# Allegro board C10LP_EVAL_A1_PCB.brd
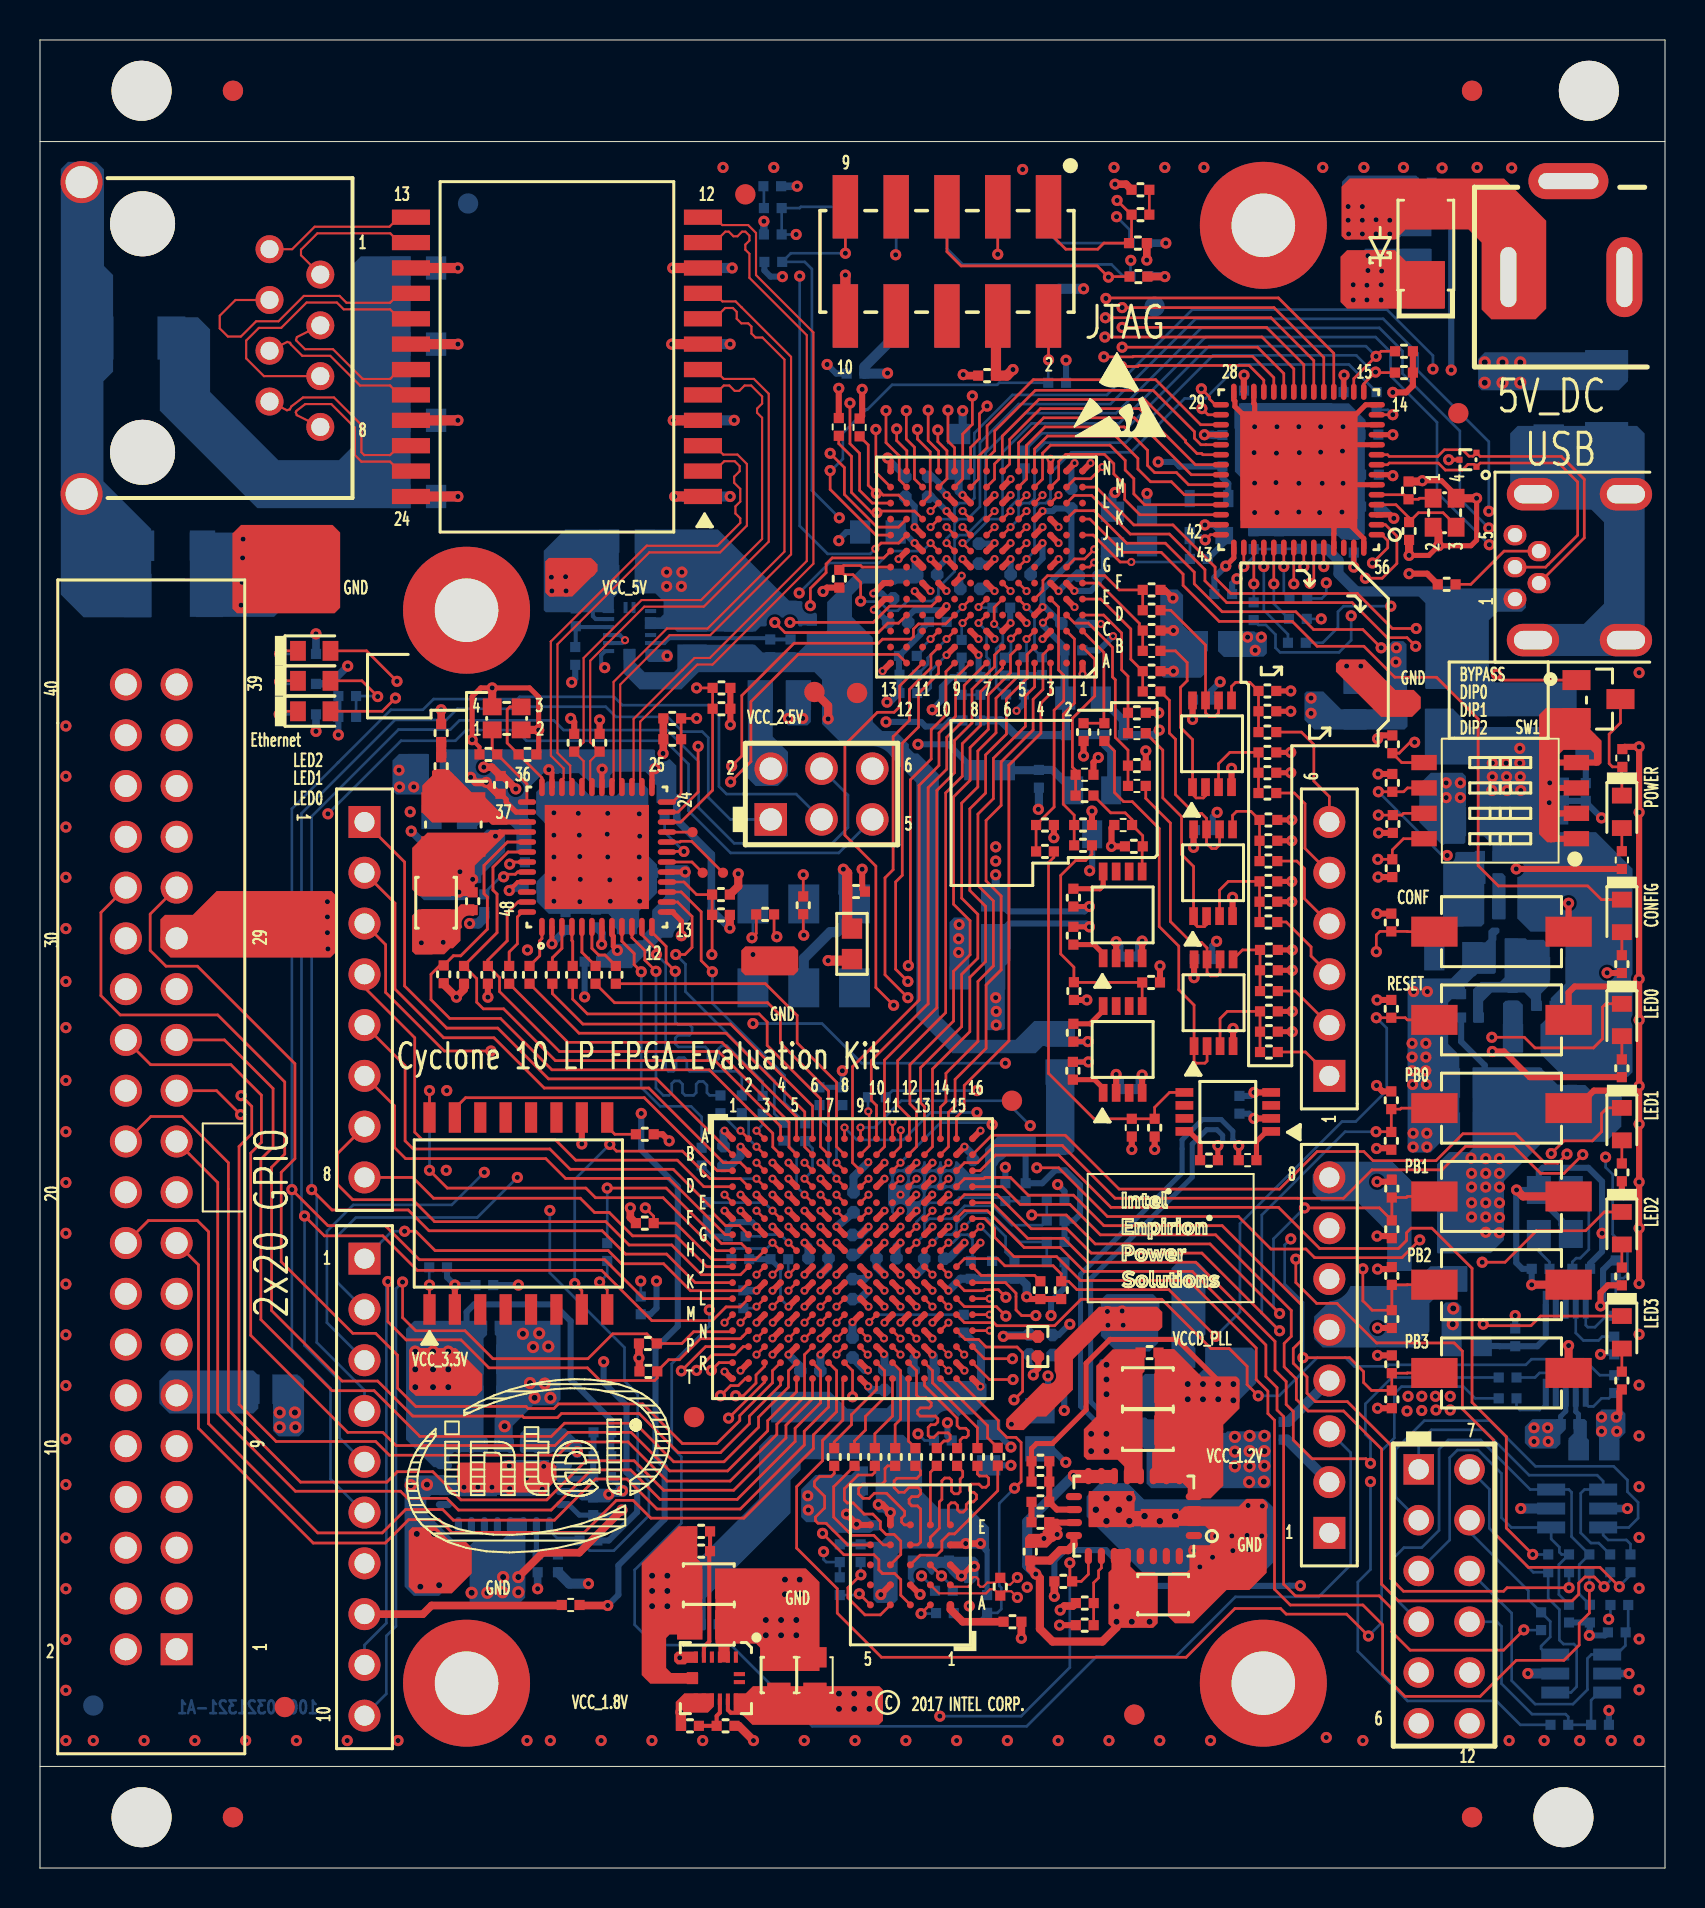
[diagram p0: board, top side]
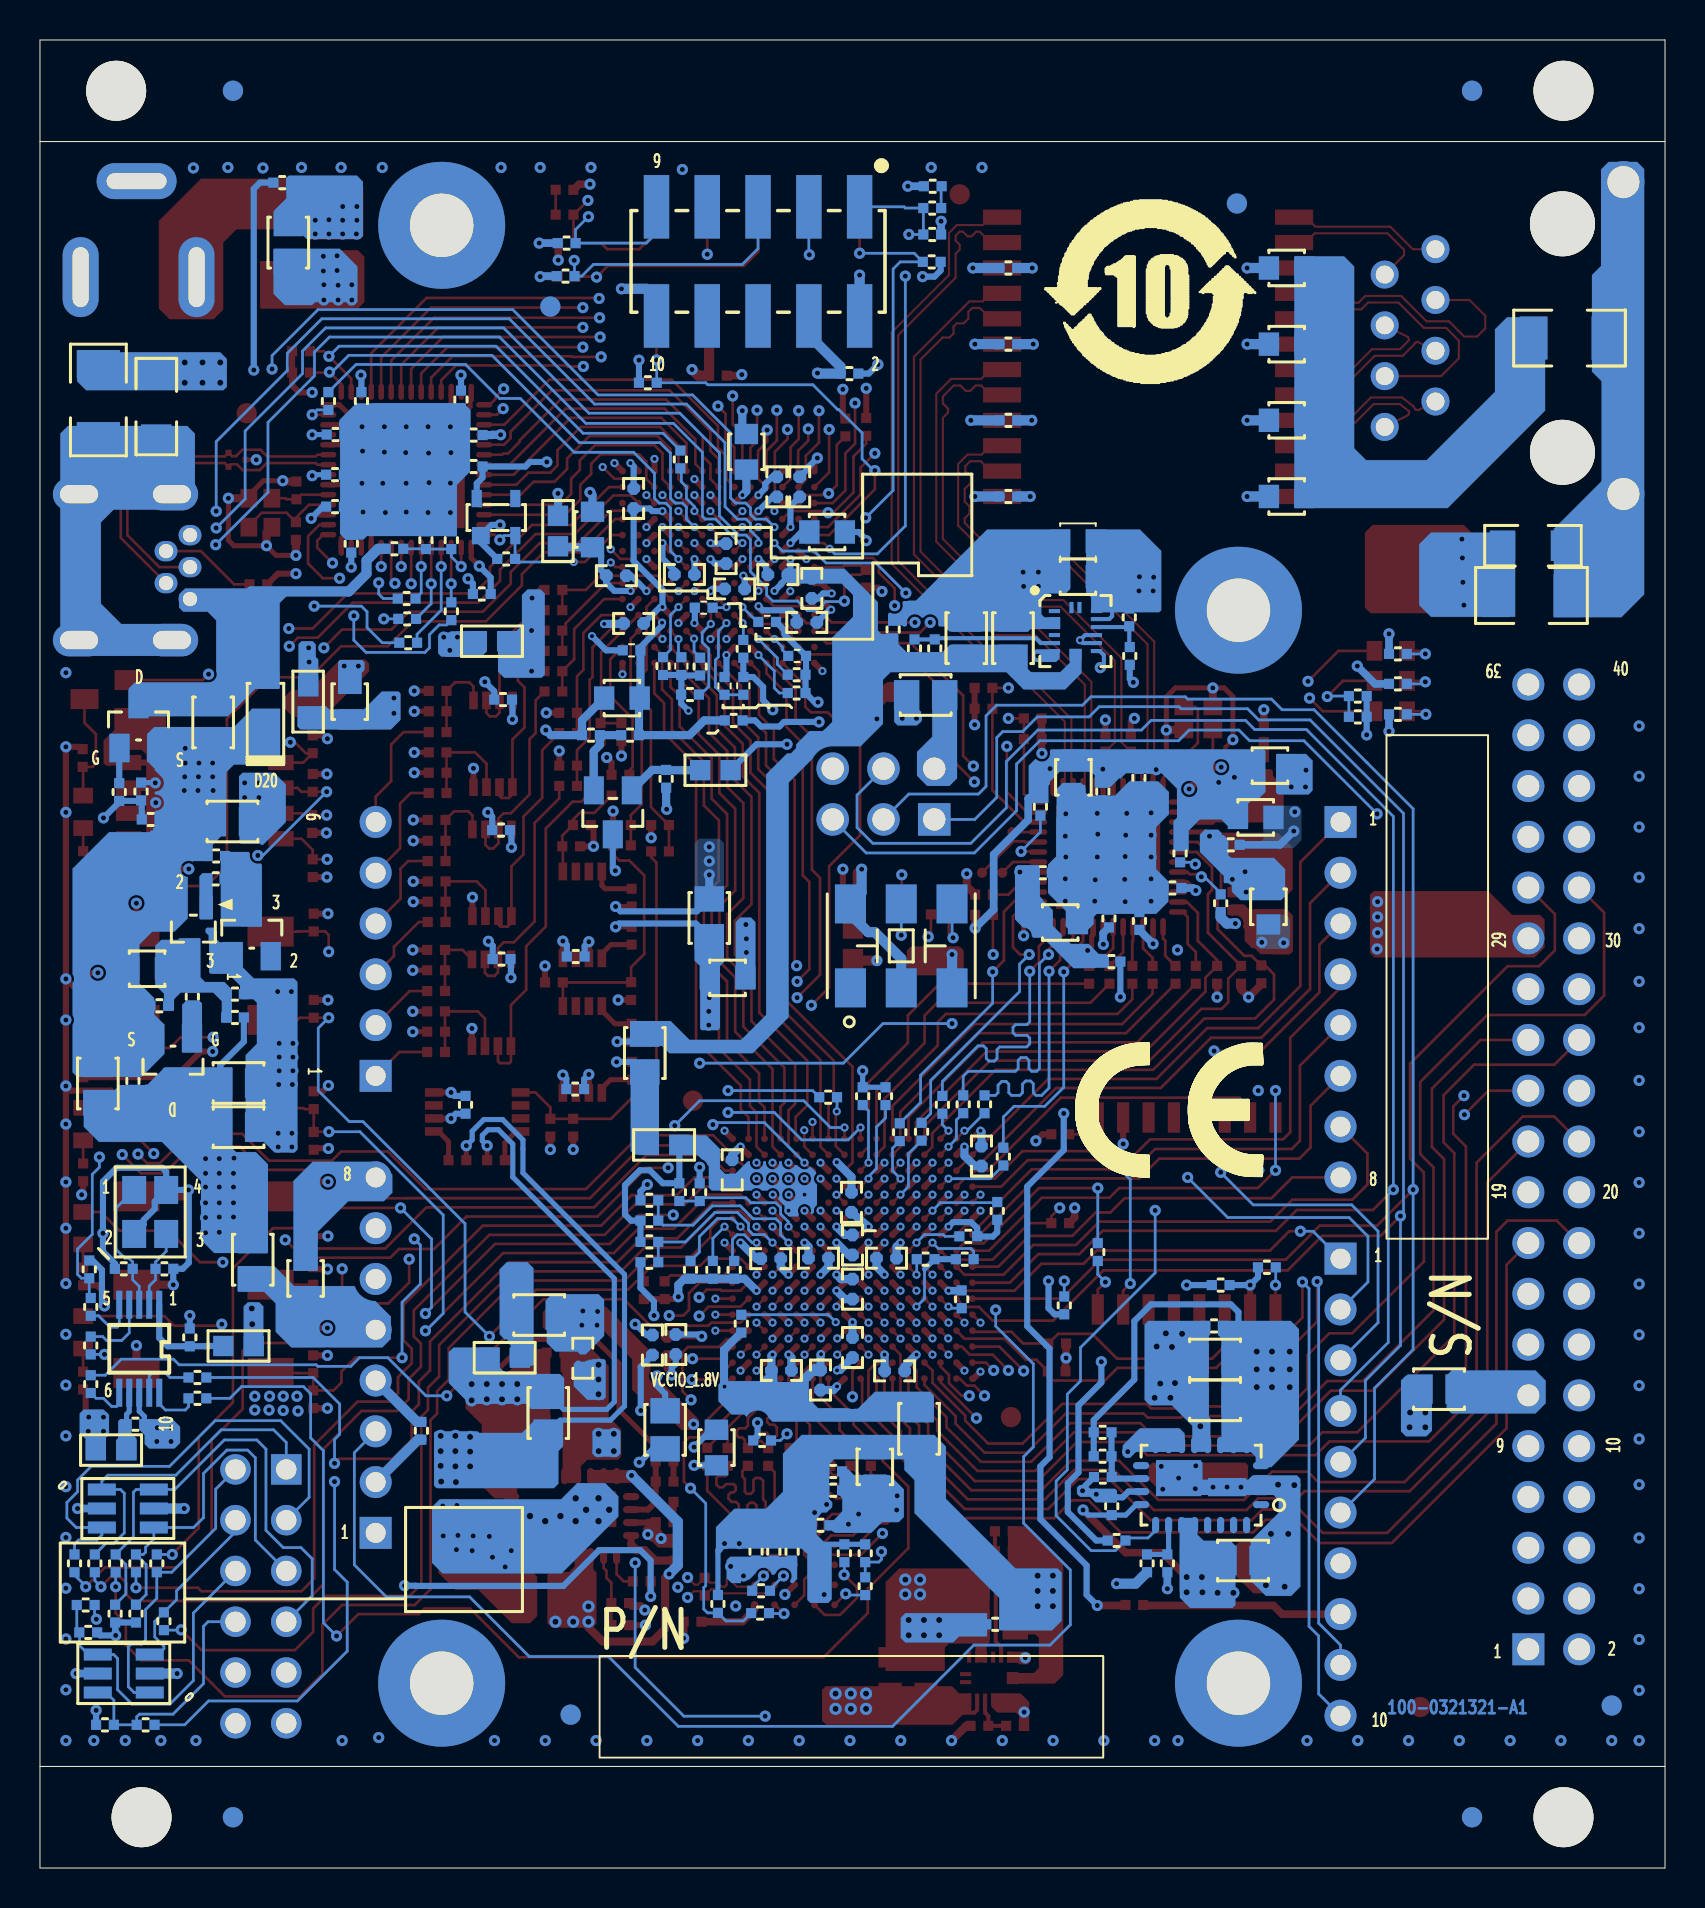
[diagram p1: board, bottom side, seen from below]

Outline 81.28 x 91.44 mm; copper layers: TOP, GND02, ART03, VCC04, GND05, BOTTOM. Coordinates in mm from the lower left corner of the outline.
Outline path: 0,86.36 81.28,86.36 ; 0,5.08 81.28,5.08 ; 0,91.44 0,0 81.28,0 81.28,91.44 0,91.44

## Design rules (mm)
net group C10_CLK50M: nets C10_CLK50M C10_CLK50M_R
net group C10_MSEL1: nets C10_MSEL1 C10_VCCA_FLT
net group DP_FX2_D_: nets FX2_D_N FX2_D_P
net group EXT_JTAG_TCK: nets EXT_JTAG_TCK N17451710
net group HBUS_CKP/HBUS_CKN: nets HBUS_CKN HBUS_CKP
net group HBUS_CS1N: nets HBUS_CS1N N17204392
net group HBUS_DQ0: nets HBUS_DQ0 N17132385
net group HBUS_DQ1: nets HBUS_DQ1 N17132392
net group HBUS_DQ2: nets HBUS_DQ2 N17132399
net group HBUS_DQ3: nets HBUS_DQ3 N17132406
net group HBUS_DQ4: nets HBUS_DQ4 N17132413
net group HBUS_DQ5: nets HBUS_DQ5 N17132420
net group HBUS_DQ6: nets HBUS_DQ6 N17132427
net group HBUS_DQ7: nets HBUS_DQ7 N17132434
net group HBUS_INTN: nets HBUS_INTN N17217865
net group HBUS_RSTON: nets HBUS_RSTON N17217821
net group HBUS_RWDS: nets HBUS_RWDS N17132441
net group M10_CLK50M: nets M10_CLK50M M10_CLK50M_R
net group M10_TCK: nets M10_TCK N16798884
net group MX1+/MX1-: nets MX1+ MX1-
net group MX2+/MX2-: nets MX2+ MX2-
net group MX3+/MX3-: nets MX3+ MX3-
net group MX4+/MX4-: nets MX4+ MX4-
net group TPIAP/TPIAN: nets TPIAN TPIAP
net group TPIBP/TPIBN: nets TPIBN TPIBP
net group TPICP/TPICN: nets TPICN TPICP
net group TPIDP/TPIDN: nets TPIDN TPIDP
net group C10_RG_TXCLK: nets ENET_RG_TXCLK
net group C10_RG_TXCTL: nets ENET_RG_TXCTL
net group C10_RG_TXD0: nets ENET_RG_TXD0
net group C10_RG_TXD1: nets ENET_RG_TXD1
net group C10_RG_TXD2: nets ENET_RG_TXD2
net group C10_RG_TXD3: nets ENET_RG_TXD3
net group CLS_I2C: nets ARDUINO_ADC_SCL ARDUINO_ADC_SDA ARDUINO_SCL ARDUINO_SDA FX2_SCL FX2_SDA MAX_SDA SYS_I2C_SCL SYS_I2C_SDA USB_SCL USB_SDA
net group ENET_RG_RX: nets RG_RXCLK RG_RXCTL RG_RXD0 RG_RXD1 RG_RXD2 RG_RXD3
net group ENET_RG_RXCLK: nets ENET_RG_RXCLK
net group ENET_RG_RXCTL: nets ENET_RG_RXCTL
net group ENET_RG_RXD0: nets ENET_RG_RXD0
net group ENET_RG_RXD1: nets ENET_RG_RXD1
net group ENET_RG_RXD2: nets ENET_RG_RXD2
net group ENET_RG_RXD3: nets ENET_RG_RXD3
net group ENET_RG_TX: nets C10_RG_TXCLK C10_RG_TXCTL C10_RG_TXD0 C10_RG_TXD1 C10_RG_TXD2 C10_RG_TXD3
net group EXT_VREF_AR: nets EXT_VREF EXT_VREF_AR N17512425

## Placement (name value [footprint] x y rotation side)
C1  0.1uF  [0402]  22.23 29.16 270 bottom
C2  0.1uF  [0402]  59.59 70.1 90 bottom
C4  12pF  [0402]  68.45 68.91 180 top
C5  12pF  [0402]  68.48 66.88 0 top
C6  0.1uF  [0402]  65.71 66.24 180 bottom
C7  0.1uF  [0402]  66.52 69.7 270 bottom
C8  0.1uF  [0402]  59.59 71.68 90 bottom
C9  0.1uF  [0402]  60.22 73.46 0 bottom
C10  0.1uF  [0402]  66.5 71.7 270 bottom
C11  0.1uF  [0402]  59.18 63.73 90 bottom
C12  0.1uF  [0402]  66.52 68.1 270 bottom
C13  0.1uF  [0402]  65.2 73.38 0 bottom
C14  0.1uF  [0402]  60.71 66.42 180 bottom
C15  DNI  [0402]  36.63 84.12 90 bottom
C16  0.1uF  [0402]  40.79 74.75 270 bottom
C17  0.1uF  [0402]  55.04 83.95 90 top
C18  0.1uF  [0402]  47.37 74.65 90 top
C19  0.1uF  [0402]  59.99 38.18 180 bottom
C20  DNI  [0402]  55.75 37.03 180 top
C22  DNI  [0402]  55.58 44.3 270 top
C23  0.1uF  [0402]  54.51 38.96 90 bottom
C26  0.1uF  [0402]  54.48 45.59 90 bottom
C28  DNI  [0402]  54.71 51.1 90 top
C29  1pF  [0402]  54.86 55.14 90 top
C30  DNI  [0402]  49.96 54.48 180 bottom
C31  DNI  [0402]  53.72 56.67 270 bottom
C32  1pF  [0402]  54.86 57.78 90 top
C33  1pF  [0402]  52.17 52.17 90 top
C34  1pF  [0402]  50.27 52.17 90 top
C35  1pF  [0402]  55.6 63.93 90 top
C36  1pF  [0402]  52.2 56.82 0 top
C37  1pF  [0402]  52.25 54.69 90 top
C38  1pF  [0402]  55.6 61.9 90 top
C39  1pF  [0402]  55.6 59.87 90 top
C40  10uF  [0603]  39.52 20.07 270 bottom
C41  0.1uF  [0402]  42.24 17.14 270 bottom
C42  0.1uF  [0402]  44.58 15.82 0 bottom
C43  0.1uF  [0402]  45.47 15.82 0 bottom
C44  27pF  [0402]  24.38 55.7 90 top
C45  22uF  [0805]  19.81 48.29 90 top
C46  330pF  [0402]  21.64 48.36 0 top
C47  330pF  [0402]  20.07 56.77 180 top
C48  10uF  [0603]  30.25 47.29 180 bottom
C49  10uF  [0603]  19.84 48.08 270 bottom
C50  0.1uF  [0402]  31.11 49.78 270 bottom
C51  0.1uF  [0402]  27.69 45.34 270 bottom
C52  0.1uF  [0402]  21.72 51.18 270 bottom
C53  27pF  [0402]  22.43 55.7 270 top
C54  DNI  [0402]  34.06 48.69 270 top
C55  DNI  [0402]  31.62 57.51 90 top
C56  DNI  [0402]  15.37 57.58 270 bottom
C57  0.1uF  [0402]  26.31 54.53 0 bottom
C58  0.1uF  [0402]  28.12 53.85 0 bottom
C59  10uF  [0603]  29.59 54.56 270 bottom
C60  0.1uF  [0402]  24.64 49.02 90 bottom
C61  0.1uF  [0402]  26.29 47.37 180 bottom
C62  0.1uF  [0402]  27.81 47.5 180 bottom
C63  10uF  [0603]  20.47 52.55 180 bottom
C64  0.1uF  [0402]  23.04 54.18 0 top
C65  DNI  [0402]  34.09 57.99 270 top
C66  DNI  [0402]  75.06 29.97 270 bottom
C67  0.1uF  [0402]  73.79 26.54 180 bottom
C72  0.1uF  [0402]  76.5 22.2 270 bottom
C73  DNI  [0402]  77.09 29.97 90 bottom
C74  0.1uF  [0402]  40.82 48.84 270 top
C76  47uF  [0805]  71.35 37.06 180 bottom
C83  22uF  [0805]  21.11 15.38 180 bottom
C84  8.2pF  [0402]  28.13 20.6 90 bottom
C85  47uF  [0805]  22.5 25.44 0 bottom
C86  47uF  [0805]  22.5 23.39 0 bottom
C87  DNI  [0402]  22.56 27.11 270 bottom
C88  DNI  [0402]  24.89 15.24 0 bottom
C89  1uF  [0402]  27.67 18.1 0 bottom
C96  22uF  [0805]  56.18 13.68 0 top
C97  8.2pF  [0402]  50.04 19.33 90 top
C98  22uF  [0805]  55.41 21.9 180 top
C99  22uF  [0805]  55.41 24 180 top
C100  DNI  [0402]  55.5 25.78 270 top
C101  DNI  [0402]  52.26 13.25 90 top
C102  1uF  [0402]  49.53 15.82 180 top
C103  DNI  [0402]  36.53 61.01 0 bottom
C104  DNI  [0402]  33.07 16.84 90 top
C105  4.7uF  [0603]  36.96 9.65 90 top
C106  4.7uF  [0603]  29.36 64.59 0 bottom
C107  10uF  [0805]  33.45 12.17 0 top
C108  10uF  [0805]  33.45 14.2 0 top
C109  10uF  [0805]  32.61 61.52 90 bottom
C110  10uF  [0805]  34.95 61.52 90 bottom
C111  DNI  [0402]  38.61 61.95 0 bottom
C112  DNI  [0402]  33.5 12.19 270 bottom
C113  DNI  [0402]  26.77 60.63 0 bottom
C114  DNI  [0402]  34.29 7.11 270 top
C115  1uF  [C0402_BGA]  54.13 25.5 270 bottom
C117  0.1uF  [C0402_BGA]  46.66 34.92 270 bottom
C120  0.01uF  [C0402_BGA]  34.19 35.61 90 bottom
C122  0.01uF  [C0402_BGA]  44.2 24.89 0 bottom
C124  0.022uF  [C0402_BGA]  40.69 33.3 90 bottom
C129  0.022uF  [C0402_BGA]  40.64 26.03 270 bottom
C130  1uF  [C0402_BGA]  49.48 26.19 270 bottom
C134  4700pF  [C0402_BGA]  40.64 28.96 90 bottom
C136  4700pF  [C0402_BGA]  44.73 30.48 0 bottom
C138  0.01uF  [C0402_BGA]  42.34 30.51 0 bottom
C139  0.01uF  [C0402_BGA]  38.94 30.51 180 bottom
C141  0.047uF  [C0402_BGA]  40.64 31.17 270 bottom
C142  0.22uF  [C0402_BGA]  50.65 26.16 270 bottom
C143  0.1uF  [C0402_BGA]  49.91 26.09 90 top
C146  4.7uF  [0603]  41.91 66.83 180 bottom
C151  0.047uF  [C0402_BGA]  46.53 63.98 180 bottom
C153  0.01uF  [C0402_BGA]  46.96 65.75 90 bottom
C155  0.01uF  [C0402_BGA]  43.28 69.09 270 bottom
C156  0.22uF  [C0402_BGA]  52.45 64.64 180 bottom
C157  0.01uF  [C0402_BGA]  49.05 64.71 180 bottom
C159  1nF/3kV  [1808]  4.78 76.53 180 bottom
C160  68pF  [0402]  32.84 80.04 270 bottom
C161  68pF  [0402]  32.84 76.23 270 bottom
C162  68pF  [0402]  32.84 72.42 270 bottom
C163  68pF  [0402]  32.84 68.61 270 bottom
C164  1nF/3kV  [1808]  6.68 63.65 0 bottom
C165  DNI  [0603]  29.36 66.37 0 bottom
C166  DNI  [0603]  38.76 9.65 90 top
C168  0.1uF  [0402]  58.19 45.47 270 bottom
C169  1nF  [0402]  61.47 42.85 90 top
C170  1nF  [0402]  61.47 45.92 90 top
C171  1nF  [0402]  61.44 49.35 90 top
C172  1nF  [0402]  61.44 52.43 90 top
C173  0.1uF  [0402]  58.22 51.92 270 bottom
C174  1nF  [0402]  61.39 55.8 90 top
C175  1nF  [0402]  61.39 58.88 90 top
C176  10uF  [0603]  53.64 66.95 90 bottom
C177  10uF  [0603]  65.79 58.34 90 bottom
C178  0.1uF  [C0402_BGA]  51.59 68.5 270 bottom
C179  0.1uF  [C0402_BGA]  42.93 62.31 0 bottom
C180  0.1uF  [C0402_BGA]  44.42 69.09 270 bottom
C181  0.1uF  [C0402_BGA]  51.59 62.26 180 bottom
C182  1uF  [C0402_BGA]  44.37 64.69 0 bottom
C183  1uF  [0402]  43.66 15.82 180 bottom
C184  0.1uF  [0402]  41.61 19.84 270 bottom
C185  1uF  [0402]  41.61 18.9 90 bottom
C188  0.1uF  [0402]  58.12 58.45 270 bottom
C189  0.22uF  [C0402_BGA]  42.67 64.01 270 bottom
C190  4.7uF  [0603]  45.95 70.84 90 bottom
C193  47uF  [0805]  50.01 21.92 270 bottom
C194  4.7uF  [0603]  47.45 21.03 270 bottom
C195  4.7uF  [0603]  46.89 44.53 180 bottom
C196  0.47uF  [C0402_BGA]  38.53 24.87 180 bottom
C197  1uF  [C0402_BGA]  42.24 24.41 270 bottom
C200  DNI  [0402]  71.53 42.55 90 bottom
C201  1uF  [0603]  75.92 44.98 180 bottom
C202  1nF/3kV  [1808]  78.36 73.43 90 bottom
C203  DNI  [0402]  76.63 39.37 0 bottom
C204  0.1uF  [0402]  67.59 42.98 180 top
C205  0.1uF  [0402]  67.59 47.29 180 top
C206  0.1uF  [0402]  67.59 38.4 180 top
C207  0.1uF  [0402]  67.61 33.99 180 top
C208  0.1uF  [0402]  67.61 29.62 180 top
C209  0.1uF  [0402]  67.61 25.2 180 top
C210  DNI  [0402]  75.74 52.45 90 bottom
C211  DNI  [0805]  71.65 52.35 180 bottom
C212  DNI  [0603]  52.17 58.52 0 bottom
C213  DNI  [0402]  51.69 60.91 90 bottom
D4  BLUE LED  [LED_0603]  79.12 52.83 90 top
D5  YELLOW_LED  [LED_0603]  79.12 47.62 90 top
D6  GREEN_LED  [LED_0603]  79.12 42.42 90 top
D7  GREEN_LED  [LED_0603]  79.12 37.21 90 top
D8  GREEN_LED  [LED_0603]  79.12 32 90 top
D9  GREEN_LED  [LED_0603]  79.12 26.8 90 top
D10  GREEN_LED  [LED_0603]  13.72 57.86 180 top
D11  GREEN_LED  [LED_0603]  13.72 59.39 180 top
D12  GREEN_LED  [LED_0603]  13.72 60.88 180 top
D20  DFLS240  [POWERDI123]  70 57.84 270 bottom
D28  BZX84C5V1 5.1V-ZENER  [SOT-23_BZX84]  70.69 46.71 180 bottom
D41  PMEG3050EP  [SOD128_CFP5]  69.32 81.18 90 top
F1  1A  [0805]  11.3 23.95 180 bottom
F2  1A  [0805]  70.64 30.43 270 bottom
F3  1A  [0805]  36.98 58.67 180 bottom
J1  DNI  [HDR2X5_100MIL_SMT]  47.9 80.37 270 bottom
J2  2X5_100mil  [HDR2X5_100MIL_SMT]  42.82 80.37 270 top
J4  61300811821  [HDR_1X8_100MIL]  64.49 16.76 90 top
J5  61301011821  [HDR_1X10_100MIL]  16.23 30.48 270 top
J6  61300611821  [HDR_1X6_100MIL]  64.49 39.62 90 top
J7  61300811821  [HDR_1X8_100MIL]  16.23 52.32 270 top
J8  2x6 PMOD Connector  [HDR2X6_100MIL]  68.96 19.94 0 top
J10  Header 2x20 Shrouded  [HDR_2X20_100MIL_TH_SR]  6.84 10.94 90 top
J12  DC Input Jack  [JACK-DC_2MM_WE]  79.25 79.58 270 top
J16  615008140121  [RJ45_615008140121]  5.13 76.53 270 top
J17  USB MINI-B  [WURTH_USB_MINI-B]  74.68 65.07 90 top
J18  61300621121  [HDR_2X3_100MIL_TH]  36.55 52.45 90 top
L2  1.5A, 180 Ohm FB  [IND_0603]  55.37 66.88 270 bottom
L3  1.5A, 180 Ohm FB  [IND_0603]  67.87 58.34 270 bottom
L5  DNI  [IND_0603]  47.5 54.91 0 bottom
L9  4.7uH  [IND_744028004]  20.68 52.2 180 top
L10  1.5A, 180 Ohm FB  [IND_0603]  71.35 26.11 0 bottom
L12  1.5A, 180 Ohm FB  [IND_0603]  40.61 46.23 90 top
L14  1.5A, 180 Ohm FB  [IND_0603]  58.67 61.37 180 bottom
L15  1.5A, 180 Ohm FB  [IND_0603]  58.04 25.53 180 bottom
L16  1.5A, 180 Ohm FB  [IND_0603]  77.72 20.9 0 bottom
L17  1.5A, 180 Ohm FB  [IND_0603]  50.06 36.17 180 bottom
NOREF  -  []  0 86.36 0 top
NOREF#2  -  [unnamed#2]  9.65 2.54 0 top
NOREF#3  -  [unnamed#2]  54.74 7.67 0 top
NOREF#4  -  [unnamed#2]  40.87 58.78 0 top
NOREF#5  -  []  81.28 0 90 top
NOREF#6  -  [unnamed#2]  70.94 72.77 0 top
NOREF#7  -  [unnamed#3]  61.19 82.17 180 top
NOREF#8  -  [unnamed#2]  71.63 88.9 0 top
NOREF#9  -  [unnamed#3]  61.19 9.25 90 top
NOREF#10  -  [unnamed#3]  21.34 62.92 90 top
NOREF#11  -  [unnamed#3]  77.47 88.9 0 top
NOREF#12  -  [unnamed#2]  9.65 88.9 0 top
NOREF#13  -  []  79.38 5.08 90 top
NOREF#14  -  []  81.03 86.36 90 top
NOREF#15  -  [unnamed#2]  32.72 22.56 0 top
NOREF#16  -  [unnamed#2]  35.28 83.72 0 top
NOREF#17  -  [unnamed#2]  48.62 38.38 0 top
NOREF#18  -  [unnamed#2]  12.24 8.05 0 top
NOREF#19  -  [unnamed#3]  21.34 9.25 90 top
NOREF#20  -  []  81.15 0 90 top
NOREF#21  -  [unnamed#2]  71.63 2.54 0 top
NOREF#22  -  [unnamed#3]  76.2 2.54 0 top
NOREF#23  -  [unnamed#3]  5.08 2.54 0 top
NOREF#24  -  [unnamed#3]  5.08 88.9 0 top
NOREF#25  -  [unnamed#2]  71.63 2.54 180 bottom
NOREF#26  -  [unnamed#2]  21.41 83.26 180 bottom
NOREF#27  -  [unnamed#2]  2.67 8.13 180 bottom
NOREF#28  -  [unnamed#2]  9.65 2.54 180 bottom
NOREF#29  -  [unnamed#2]  71.63 88.9 180 bottom
NOREF#30  -  [unnamed#2]  9.65 88.9 180 bottom
NOREF#31  -  [unnamed#2]  55.75 78.11 180 bottom
NOREF#32  -  [unnamed#2]  54.74 7.67 180 bottom
Q5  FDV305N  [SOT23]  77.95 58.47 270 top
Q15  DMG2305UX  [SOT-23]  74.63 40.41 0 bottom
Q29  MMST3906-7-F  [SOT-323]  73.61 46.99 0 bottom
Q30  DMG2305UX  [SOT-23]  76.35 57.12 180 bottom
R1  10K  [0402]  33.4 32.87 0 bottom
R2  10K  [0402]  34.85 31.6 270 bottom
R4  10K  [0402]  35.03 30.45 90 bottom
R6  1K  [0402]  30.25 32.26 270 top
R7  10K  [0402]  36.98 30.45 270 bottom
R8  0  [0402]  30.05 28.14 0 bottom
R9  0  [0402]  19.91 30.05 90 bottom
R10  24.9  [0402]  28.37 30.81 180 bottom
R11  0  [0402]  30.25 36.7 90 top
R12  49.9  [0402]  46.2 27.23 0 bottom
R13  49.9  [0402]  45.16 21.39 90 bottom
R16  10K  [0402]  46.56 29.92 0 bottom
R17  0  [0402]  49.3 33.81 0 bottom
R18  DNI  [0402]  48.29 33.81 0 bottom
R19  DNI  [0402]  50.8 32.38 270 bottom
R20  0  [0402]  50.8 33.4 270 bottom
R21  10K  [0402]  47.62 29.92 0 bottom
R22  0  [0402]  50.8 31.32 270 bottom
R23  DNI  [0402]  50.8 30.3 270 bottom
R26  0  [0402]  49.25 70.46 0 bottom
R27  100K  [0402]  57.96 65.48 270 bottom
R28  DNI  [1206]  6.6 66.14 180 bottom
R29  2K  [0402]  68.22 74.8 90 top
R30  2K  [0402]  68.22 75.87 90 top
R31  10K  [0402]  63.55 65.99 90 bottom
R32  20K  [0402]  61.98 66.42 180 bottom
R33  10K  [0402]  50.11 60.12 0 bottom
R34  0  [0402]  62.87 61.29 270 bottom
R35  0  [0402]  60.71 62.86 180 bottom
R36  0  [0402]  62.92 62.48 270 bottom
R37  0  [0402]  62.94 63.5 270 bottom
R38  10K  [0402]  43.43 58.78 270 bottom
R39  10K  [0402]  46.1 60.99 0 bottom
R40  10K  [0402]  47.04 59.13 180 bottom
R41  10K  [0402]  48.08 63.04 90 bottom
R42  10K  [0402]  49.2 60.12 0 bottom
R43  10K  [0402]  48.26 60.1 0 bottom
R44  DNI  [0402]  36.65 83.03 270 bottom
R45  1K  [0402]  36.65 81.71 90 bottom
R46  10K  [0402]  54.99 79.63 90 bottom
R47  10K  [0402]  54.94 81.28 90 bottom
R50  DNI  [0402]  46.1 59.13 0 bottom
R51  1K  [0402]  43.43 59.69 90 bottom
R52  1K  [0402]  48.77 58.7 270 bottom
R53  1K  [0402]  43.41 60.63 90 bottom
R54  1K  [0402]  44.91 62.33 90 bottom
R55  2K  [0402]  39.98 64.49 180 top
R56  2K  [0402]  78.82 29.95 180 bottom
R57  DNI  [0402]  55.04 82.7 270 top
R58  1K  [0402]  54.91 81.28 90 top
R59  1K  [0402]  50.88 74.3 270 bottom
R60  10K  [0402]  54.94 79.6 270 top
R61  10K  [0402]  36.68 80.34 270 bottom
R63  0.03  [0805]  55.85 22.76 90 bottom
R64  0.2  [0805]  51.03 40.77 90 bottom
R65  100  [0402]  60.4 35.41 270 top
R66  100  [0402]  58.47 35.41 90 top
R67  100  [0402]  51.66 39.88 180 top
R68  100  [0402]  51.69 41.78 0 top
R71  4.99K  [0402]  54.61 37.03 180 top
R72  4.99K  [0402]  51.71 43.87 180 top
R77  0.2  [0805]  47.8 47.52 90 bottom
R78  100  [0402]  51.69 46.63 180 top
R79  100  [0402]  51.69 48.54 0 top
R81  4.99K  [0402]  54.18 52.17 90 top
R83  10  [0402]  54.86 54.13 90 top
R84  10  [0402]  54.86 56.77 90 top
R85  10  [0402]  52.17 51.16 90 top
R86  10  [0402]  50.27 50.85 90 top
R87  10  [0402]  55.6 62.92 90 top
R88  10  [0402]  53.24 56.82 0 top
R89  10  [0402]  52.25 53.64 90 top
R90  10  [0402]  55.6 60.88 90 top
R91  10  [0402]  55.6 58.85 90 top
R92  0  [0402]  48.64 12.32 270 top
R95  5.1  [0402]  20.07 55.12 180 top
R96  1K  [0402]  34.06 47.68 90 top
R97  1K  [0402]  22.4 44.68 0 top
R98  1K  [0402]  21.21 44.68 0 top
R99  1K  [0402]  31.24 53.09 0 bottom
R100  499  [0402]  24.26 50.75 180 bottom
R101  10K  [0402]  22.23 48.26 0 bottom
R102  33  [0402]  28.8 44.68 180 top
R103  33  [0402]  23.47 44.68 180 top
R104  33  [0402]  27.79 44.68 180 top
R105  33  [0402]  26.64 44.68 180 top
R106  33  [0402]  25.63 44.68 180 top
R107  33  [0402]  24.49 44.68 180 top
R108  16K  [0402]  26.72 56.29 0 top
R109  11K  [0402]  31.62 56.46 90 top
R110  16K  [0402]  27.99 56.29 0 top
R112  11K  [0402]  15.37 58.62 270 bottom
R114  3.92K  [0402]  34.09 59.03 270 top
R116  200  [0402]  78.54 15.24 0 bottom
R117  200  [0402]  75.44 15.24 0 bottom
R118  200  [0402]  79.55 15.24 0 bottom
R119  200  [0402]  75.08 12.34 180 bottom
R120  200  [0402]  76.48 15.24 0 bottom
R121  200  [0402]  78.99 13.16 90 bottom
R122  200  [0402]  77.5 15.24 0 bottom
R123  200  [0402]  76 7.16 90 bottom
R135  390  [0402]  79.12 45.21 180 top
R136  10K  [0402]  51.08 28.91 180 top
R137  10K  [0402]  67.59 36.37 0 top
R138  390  [0402]  79.12 40 180 top
R139  10K  [0402]  67.61 31.95 0 top
R140  390  [0402]  79.12 34.8 180 top
R141  10K  [0402]  67.61 27.46 0 top
R142  390  [0402]  79.12 29.59 180 top
R143  390  [0402]  79.12 24.38 180 top
R144  10K  [0402]  67.61 23.44 0 top
R145  10K  [0402]  67.64 50.01 0 top
R146  10K  [0402]  67.67 52.22 0 top
R147  10K  [0402]  67.64 54.28 180 top
R148  10K  [0402]  67.64 56.21 180 top
R152  0  [0402]  73.41 23.49 90 bottom
R155  0  [0402]  73.41 24.54 90 bottom
R157  0  [0402]  78.74 24.21 0 bottom
R160  33  [0402]  36.27 47.7 90 top
R162  33  [0402]  38.18 48.16 180 top
R164  DNI  [0805]  68.86 81.31 270 bottom
R165  DNI  [0805]  72.62 57.3 270 bottom
R173  1K  [0805]  71.35 39.27 180 bottom
R178  100K  [0402]  27.43 16.38 90 bottom
R179  10K  [0402]  25.91 15.24 180 bottom
R180  348K  [0402]  28.13 21.79 270 bottom
R181  76.8K  [0402]  28.12 19.56 90 bottom
R189  100K  [0402]  51.18 14.34 90 top
R190  10K  [0402]  52.26 12.15 270 top
R191  348K  [0402]  50.04 20.35 270 top
R192  340K  [0402]  50.04 18.31 90 top
R197  0  [0402]  33.07 15.85 90 top
R198  0  [0402]  37.54 61.01 0 bottom
R199  10K  [0402]  32.51 7.11 270 top
R200  10K  [0402]  26.8 62.56 0 bottom
R201  0  [0402]  50.04 17.3 90 top
R207  10K  [0402]  50.04 28.91 180 top
R208  75  [0603]  18.92 80.04 180 bottom
R209  75  [0603]  18.92 76.23 180 bottom
R210  75  [0603]  18.92 72.42 180 bottom
R211  75  [0603]  18.92 68.61 180 bottom
R213  DNI  [0402]  70.36 64.21 270 top
R214  2K  [0402]  39.95 72.09 0 top
R215  2K  [0402]  41 72.06 0 top
R216  316  [0402]  61.47 41.83 270 top
R217  316  [0402]  61.47 40.82 270 top
R218  316  [0402]  61.47 44.91 270 top
R219  316  [0402]  61.47 43.87 270 top
R220  316  [0402]  61.44 48.34 270 top
R221  316  [0402]  61.44 47.32 270 top
R222  316  [0402]  61.44 51.38 270 top
R223  316  [0402]  61.44 50.37 270 top
R224  316  [0402]  61.39 54.79 270 top
R225  316  [0402]  61.39 53.77 270 top
R226  316  [0402]  61.39 57.86 270 top
R227  316  [0402]  61.39 56.82 270 top
R228  DNI  [0402]  46.58 57.4 90 bottom
R235  1K  [0402]  79.12 50.42 180 top
R236  0.2  [0805]  37.31 21.97 90 bottom
R237  0.2  [0805]  56.31 27.66 180 bottom
R240  390  [0402]  13.36 57.71 90 bottom
R241  390  [0402]  13.36 59.23 90 bottom
R242  390  [0402]  13.36 60.73 90 bottom
R243  100  [0402]  48.03 14.07 0 top
R245  10K  [0402]  41.05 15.75 0 bottom
R246  10K  [0402]  48.74 29.92 0 bottom
R247  0  [0402]  66.85 73.38 180 bottom
R248  0  [0402]  41.86 38.56 90 bottom
R249  33  [0402]  43.79 20.56 0 top
R250  33  [0402]  45.87 20.56 0 top
R251  33  [0402]  41.76 20.56 0 top
R252  33  [0402]  40.74 20.56 0 top
R253  33  [0402]  39.73 20.56 0 top
R254  33  [0402]  42.77 20.56 0 top
R255  33  [0402]  44.86 20.56 0 top
R256  33  [0402]  46.89 20.56 0 top
R257  33  [0402]  47.9 20.57 0 top
R258  DNI  [0402]  45.21 13.87 90 bottom
R259  DNI  [0402]  45.26 12.75 270 bottom
R260  DNI  [0402]  40.01 14.1 0 bottom
R261  DNI  [0402]  47.37 13.21 0 bottom
R262  DNI  [0402]  40.01 15.75 0 bottom
R263  0  [0402]  78.74 26.14 0 bottom
R264  0  [0402]  78.74 28.07 180 bottom
R265  DNI  [0402]  78.87 11.79 90 bottom
R266  DNI  [0402]  78.03 7.16 270 bottom
R269  DNI  [0402]  77.52 12.73 180 bottom
R270  DNI  [0402]  76.48 12.73 180 bottom
R275  DNI  [0603]  68 29.49 270 bottom
R276  2K  [0402]  30.43 24.84 90 top
R277  2K  [0402]  30.4 26.24 90 top
R278  2K  [0402]  40.13 38.61 180 bottom
R279  2K  [0402]  38.99 38.61 180 bottom
R280  0  [0402]  62.2 21.87 180 bottom
R288  10K  [0402]  35.18 28.45 180 bottom
R289  390  [0402]  72.47 50.62 90 bottom
R290  10K  [0402]  72.49 49.48 90 bottom
R291  10K  [0402]  71.53 43.71 90 bottom
R292  100K  [0402]  75.31 43.13 90 bottom
R293  DNI  [1206]  75.46 73.1 270 bottom
R294  10  [0402]  73.66 43.59 0 bottom
R295  DNI  [0402]  51.77 56.67 90 bottom
R296  DNI  [0805]  78.38 39.24 270 bottom
R297  DNI  [0402]  20.19 44.7 0 top
R298  1K  [0402]  76.23 53.85 0 bottom
R299  10  [0402]  77.32 53.82 180 bottom
R300  0  [0402]  69.16 84.3 270 bottom
R301  33  [0402]  38.28 36.8 180 bottom
R302  33  [0402]  34.04 38.2 180 bottom
R303  33  [0402]  36.14 38.18 180 bottom
R304  33  [0402]  35.1 38.2 180 bottom
R305  33  [0402]  33.1 35.59 180 bottom
R306  33  [0402]  37.19 36.83 180 bottom
R307  0  [0603]  19.76 55.14 0 bottom
R308  DNI  [0402]  26.54 13.16 90 top
R309  DNI  [0402]  79.15 55.52 0 top
S1  PB Switch  [WURTH_6X3P5_TACT_SWITCH]  73.1 46.84 180 top
S2  PB Switch  [WURTH_6X3P5_TACT_SWITCH]  73.1 42.42 180 top
S3  PB Switch  [WURTH_6X3P5_TACT_SWITCH]  73.1 38.01 180 top
S4  PB Switch  [WURTH_6X3P5_TACT_SWITCH]  73.1 33.59 180 top
S5  PB Switch  [WURTH_6X3P5_TACT_SWITCH]  73.1 29.18 180 top
S6  PB Switch  [WURTH_6X3P5_TACT_SWITCH]  73.1 24.77 180 top
SW1  DIPSWITCH4  [DIPSWITCH_SMT_QUAD]  73.04 51.49 90 top
TP5  VIA_1  [TP_020RD_SMT]  32.64 51.82 0 top
TP6  VIA_1  [TP_020RD_SMT]  33.15 49.78 0 top
TP7  VIA_1  [TP_020RD_SMT]  34.16 49.78 90 top
TP12  VIA_1  [TP_040RD_SMT]  14.05 64.59 180 top
TP13  VIA_1  [TP_040RD_SMT]  20.98 14.96 0 top
TP14  VIA_1  [TP_040RD_SMT]  60.66 14.94 270 top
TP15  VIA_1  [TP_040RD_SMT]  68.43 58.29 270 top
TP16  VIA_1  [TP_040RD_SMT]  37.13 45.24 90 top
TP17  VIA_1  [TP_040RD_SMT]  36.14 14.2 90 top
TP18  VIA_1  [TP_040RD_SMT]  27.36 65.02 180 top
TP19  VIA_1  [TP_040RD_SMT]  21.56 24.18 270 top
TP20  VIA_1  [TP_040RD_SMT]  58.68 21.95 270 top
TP21  VIA_1  [TP_040RD_SMT]  38.73 58.83 90 top
TP22  VIA_1  [TP_040RD_SMT]  30.66 9.83 90 top
TP25  VIA_1  [TP_040RD_SMT]  44.73 23.39 90 bottom
TP26  VIA_1  [TP_040RD_SMT]  55.5 27.56 0 top
TP27  VIA_1  [TP_040RD_SMT]  57.4 29.72 180 bottom
U1  10CL025YU256I7G  [U256]  40.64 30.48 0 top
U2  EPCQ64  [SOIC-16_EPCQ]  23.93 32.74 0 top
U3  10M08SAU169  [BGA169-0R80-11X11]  47.35 65.07 180 top
U4  ADM811  [SOT-143]  58.47 67.56 90 bottom
U5  TPD2EUSB30  [DRT]  71.42 70.44 90 top
U6  CY7C68013A_QFN  [QFN56]  62.96 69.94 180 top
U7  LT6105IMS8  [MSOP-8]  59.41 37.82 90 top
U8  LT6105IMS8  [MSOP-8]  54.15 40.94 0 top
U11  LT6105IMS8  [MSOP-8]  54.15 47.68 0 top
U12  REF3130/DNI  [SOT23-3]  52.63 52.81 0 bottom
U13  IS66WVH16M8ALL-166B1LI  [TFBGA-24_6X8]  43.54 15.16 180 top
U14  PEF7071  [VQFN-48_PEF7071]  27.86 50.57 90 top
U15  824013  [SOT23-6L]  76.89 17.98 270 bottom
U16  824013  [SOT23-6L]  77.09 9.73 90 bottom
U20  510MCA50M0000AAGR  [SI510]  38.2 46.13 180 bottom
U23  -  [EN5339QI]  23.2 19.15 0 bottom
U25  EN5329QI  [EN5339QI]  54.71 17.6 180 top
U26  EP5358HUI  [UQFN16]  33.81 9.5 270 top
U27  EP5358HUI  [UQFN16]  29.49 61.87 180 bottom
U28  749020010A  [LAN_XFMR_749020010A]  25.86 75.59 90 top
U31  Si5351A-B07321-GT  [MSOP-10_SI5351]  76.32 25.97 270 bottom
U32  MCP6242-E/MS  [MSOP-8]  58.7 43.28 0 top
U33  MCP6242-E/MS  [MSOP-8]  58.67 49.78 0 top
U34  MCP6242-E/MS  [MSOP-8]  58.62 56.24 0 top
Y1  24.00MHz  [XTAL_FA-128]  70.26 67.79 270 top
Y2  25.00MHz  [XTAL_FA-128]  23.34 57.51 0 top
Y3  25.00MHz  [XTAL_FA-238]  75.77 32.82 270 bottom

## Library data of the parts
C1 C2 C4-C20 C22 C23 C26 C28 C29 C31-C39 C41-C44 C46 C47 C50-C58 C60-C62 C64 C65 C67 C72 C74 C88 C101 C103 C104 C113 C114 C160-C163 C168-C175 C184 C188 C200 C203-C210 C213 = CAP: Tolerance: TOL; User Part Number: PART#
C30 = Cap 0.47UF -20%+80% 10V 0402: Tolerance: TOL; User Part Number: PART#
C40 C45 C48 C49 C59 C63 C76 C85 C86 C107-C110 C117 C120 C122 C124 C129 C134 C136 C138 C139 C141-C143 C151 C153 C155-C157 C159 C164 C176-C181 C189 C193 C196 C201 C202 C211 C212 = CAP
C66 C73 = Cap 18PF 5% 50V 0402: Tolerance: TOL; User Part Number: PART#
C83 C96 C98 C99 C105 C106 C146 C165 C166 C190 C194 C195 = Cap 0.1UF +/-10% 10V 0402
C84 C97 = Cap 0.1UF +/-10% 10V 0402: Tolerance: TOL; User Part Number: PART#
C87 C89 C100 C102 C111 C112 C183 C185 = CAP 1.0UF 10% 10V 0402: Tolerance: TOL; User Part Number: PART#
C115 C130 C182 C197 = CAP 1.0UF 10% 10V 0402
D4 = LED
D5-D12 = LED_WURTH_1
D20 = ZC2800E/SOT
D28 = ZENERDIODE_2: Tolerance: *; User Part Number: *
D41 = D-SCHOTTKY_0
F1-F3 = FUSE
J1 J2 = 2x5: User Part Number: *; Tolerance: *
J4 J7 = 61300811821
J5 = 61300811821_1
J6 = 61300811821_0
J8 = 2x6 PMOD
J10 = 2x10_0
J12 = Jack-DC
J16 = 615008137421_0: Tolerance: ?; User Part Number: RJ45
J17 = USB MINI-B
J18 = hdr2x3_87227
L2 L3 L5 L10 L12 L14-L17 = IND Ferrite 0603 3A/30 Ohms: User Part Number: *; Tolerance: *
L9 = INDUCTOR
Q5 = PWRMOSFET_EN_GSD_0
Q15 Q30 = DMP3098L: User Part Number: *; Tolerance: *
Q29 = MMBT3906/SOT_0
R1 R2 R4 R7 R16 R21 R31 R33 R38-R43 R46 R47 R50 R60 R61 R100 R101 R136 R137 R139 R141 R144-R148 R179 R190 R199 R200 R207 R216-R227 R245 R246 R261 R262 R288 R290 R291 = RES 10K OHM 5% 1/16W 0402 SMD: Tolerance: TOL; User Part Number: PART#
R6 R45 R51-R54 R58 R59 R96-R99 R135 R138 R140 R142 R143 R235 R240-R242 R289 R297 R298 = R: Tolerance: TOL; User Part Number: PART#
R8 R9 R11 R17 R20 R22 R26 R27 R29 R30 R32 R34-R37 R55 R56 R65-R68 R71 R72 R78 R79 R81 R92 R95 R108-R110 R112 R114 R116-R123 R152 R155 R157 R178 R180 R181 R189 R191 R192 R197 R198 R201 R214 R215 R243 R247 R248 R263 R264 R276-R280 R292 R300 R308 R309 = RESISTOR: Tolerance: TOL; User Part Number: PART#
R10 = RES 24.9 OHM 1% 1/16W 0402: Tolerance: TOL; User Part Number: PART#
R12 R13 = RES 49.9 OHM 1% 1/16W 0402: Tolerance: TOL; User Part Number: PART#
R18 R19 R23 R44 R57 R213 R228 R258-R260 R265 R266 R269 R270 R295 = RESISTOR: Tolerance: TOL; User Part Number: PART#; signal model: RESISTOR_0402_DNI_DNI
R28 R63 R64 R77 R164 R165 R173 R208-R211 R236 R237 R275 R293 R296 R307 = RESISTOR
R83-R91 R294 R299 = RES 10 OHM 1.0% 1/16W 0402: Tolerance: TOL; User Part Number: PART#
R102-R107 R160 R162 R249-R257 R301-R306 = RESISTOR: Tolerance: TOL; User Part Number: PART#; signal model: RESISTOR_0402_33_33
S1-S6 = TS-A02SA-2-S100_0: User Part Number: *
SW1 = SPST4
TP5-TP7 = VIA_1: Tolerance: *; User Part Number: *
TP12-TP22 TP25-TP27 = VIA_1: User Part Number: *; Tolerance: *
U1 = 10CL025YU256I7G
U2 = EPCQ128
U3 = 10M16SA U169_12
U4 = MAX811_0: User Part Number: PART#; Tolerance: TOL
U5 = TPD2EUSB30_0: Tolerance: *; User Part Number: *
U6 = CY7C68013A_0: User Part Number: *
U7 U8 U11 = LT6105IDCB_0
U12 = REF3125_1
U13 = IS66WVH32M8ALL-166BLI_0
U14 = PEF7071
U15 U16 = 824013
U20 = Si510-DualCMOS_0: Tolerance: ?; User Part Number: XOS006RM01A
U23 U25 = EN5329/5339QI_0
U26 U27 = EP5358xUI
U28 = 749020010A
U31 = Si5351A-B-GT: Tolerance: ?; User Part Number: MSOP-10_Si5351
U32-U34 = MCP6242-E/MS
Y1 = CRYSTAL_SM_13: User Part Number: *
Y2 = XTAL 25MHz 30PPM 18pF mini: User Part Number: *
Y3 = XTAL 25MHz 30PPM 18pF mini: Tolerance: ?; User Part Number: XTAL_FA-238

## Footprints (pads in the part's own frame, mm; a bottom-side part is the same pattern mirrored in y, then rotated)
0402
  rect 0.508x0.508 smd: 1(0,0.445) 2(0,-0.445)
0603
  rect 1.016x1.168 smd: 1(-0.889,0) 2(0.889,0)
0805
  rect 1.27x1.473 smd: 1(-0.953,0) 2(0.953,0)
1206
  rect 1.27x1.524 smd: 1(-1.524,0) 2(1.524,0)
1808
  rect 1.397x2.159 smd: 1(-1.8,0) 2(1.8,0)
BGA169-0R80-11X11
  round 0.34 smd: A1(-4.8,4.8) A2(-4,4.8) A3(-3.2,4.8) A4(-2.4,4.8) A5(-1.6,4.8) A6(-0.8,4.8) A7(0,4.8) A8(0.8,4.8) A9(1.6,4.8) A10(2.4,4.8) A11(3.2,4.8) A12(4,4.8) A13(4.8,4.8) B1(-4.8,4) B2(-4,4) B3(-3.2,4) B4(-2.4,4) B5(-1.6,4) B6(-0.8,4) B7(0,4) B8(0.8,4) B9(1.6,4) B10(2.4,4) B11(3.2,4) B12(4,4) B13(4.8,4) C1(-4.8,3.2) C2(-4,3.2) C3(-3.2,3.2) C4(-2.4,3.2) C5(-1.6,3.2) C6(-0.8,3.2) C7(0,3.2) C8(0.8,3.2) C9(1.6,3.2) C10(2.4,3.2) C11(3.2,3.2) C12(4,3.2) C13(4.8,3.2) D1(-4.8,2.4) D2(-4,2.4) D3(-3.2,2.4) D4(-2.4,2.4) D5(-1.6,2.4) D6(-0.8,2.4) D7(0,2.4) D8(0.8,2.4) D9(1.6,2.4) D10(2.4,2.4) D11(3.2,2.4) D12(4,2.4) D13(4.8,2.4) E1(-4.8,1.6) E2(-4,1.6) E3(-3.2,1.6) E4(-2.4,1.6) E5(-1.6,1.6) E6(-0.8,1.6) E7(0,1.6) E8(0.8,1.6) E9(1.6,1.6) E10(2.4,1.6) E11(3.2,1.6) E12(4,1.6) E13(4.8,1.6) F1(-4.8,0.8) F2(-4,0.8) F3(-3.2,0.8) F4(-2.4,0.8) F5(-1.6,0.8) F6(-0.8,0.8) F7(0,0.8) F8(0.8,0.8) F9(1.6,0.8) F10(2.4,0.8) F11(3.2,0.8) F12(4,0.8) F13(4.8,0.8) G1(-4.8,0) G2(-4,0) G3(-3.2,0) G4(-2.4,0) G5(-1.6,0) G6(-0.8,0) G7(0,0) G8(0.8,0) G9(1.6,0) G10(2.4,0) G11(3.2,0) G12(4,0) G13(4.8,0) H1(-4.8,-0.8) H2(-4,-0.8) H3(-3.2,-0.8) H4(-2.4,-0.8) H5(-1.6,-0.8) H6(-0.8,-0.8) H7(0,-0.8) H8(0.8,-0.8) H9(1.6,-0.8) H10(2.4,-0.8) H11(3.2,-0.8) H12(4,-0.8) H13(4.8,-0.8) J1(-4.8,-1.6) J2(-4,-1.6) J3(-3.2,-1.6) J4(-2.4,-1.6) J5(-1.6,-1.6) J6(-0.8,-1.6) J7(0,-1.6) J8(0.8,-1.6) J9(1.6,-1.6) J10(2.4,-1.6) J11(3.2,-1.6) J12(4,-1.6) J13(4.8,-1.6) K1(-4.8,-2.4) K2(-4,-2.4) K3(-3.2,-2.4) K4(-2.4,-2.4) K5(-1.6,-2.4) K6(-0.8,-2.4) K7(0,-2.4) K8(0.8,-2.4) K9(1.6,-2.4) K10(2.4,-2.4) K11(3.2,-2.4) K12(4,-2.4) K13(4.8,-2.4) L1(-4.8,-3.2) L2(-4,-3.2) L3(-3.2,-3.2) L4(-2.4,-3.2) L5(-1.6,-3.2) L6(-0.8,-3.2) L7(0,-3.2) L8(0.8,-3.2) L9(1.6,-3.2) L10(2.4,-3.2) L11(3.2,-3.2) L12(4,-3.2) L13(4.8,-3.2) M1(-4.8,-4) M2(-4,-4) M3(-3.2,-4) M4(-2.4,-4) M5(-1.6,-4) M6(-0.8,-4) M7(0,-4) M8(0.8,-4) M9(1.6,-4) M10(2.4,-4) M11(3.2,-4) M12(4,-4) M13(4.8,-4) N1(-4.8,-4.8) N2(-4,-4.8) N3(-3.2,-4.8) N4(-2.4,-4.8) N5(-1.6,-4.8) N6(-0.8,-4.8) N7(0,-4.8) N8(0.8,-4.8) N9(1.6,-4.8) N10(2.4,-4.8) N11(3.2,-4.8) N12(4,-4.8) N13(4.8,-4.8)
C0402_BGA
  rrect 0.635x0.635 smd: 1(-0.5,0) 2(0.5,0)
DIPSWITCH_SMT_QUAD
  rect 0.762x1.27 smd: 1(0,-3.81) 2(1.27,-3.81) 3(2.54,-3.81) 4(3.81,-3.81) 5(3.81,3.81) 6(2.54,3.81) 7(1.27,3.81) 8(0,3.81)
DRT
  rect 0.305x0.305 smd: 1(-0.35,-0.425) 2(0.35,-0.425) 3(0,0.425)
EN5339QI
  oval 0.813x0.356 smd: 1(-3,0.975) 2(-3,0.325) 3(-3,-0.325) 4(-3,-0.975) 13(3,-0.975) 14(3,-0.325) 15(3,0.325) 16(3,0.975)
  oval 0.356x0.813 smd: 5(-2.275,-2) 6(-1.625,-2) 7(-0.975,-2) 8(-0.325,-2) 9(0.325,-2) 10(0.975,-2) 11(1.625,-2) 12(2.275,-2) 17(2.275,2) 18(1.625,2) 19(0.975,2) 20(0.325,2) 21(-0.325,2) 22(-0.975,2) 23(-1.625,2) 24(-2.275,2)
  rect 1.905x0.914 smd: 25(-1.3,0.1)
  rect 2.261x1.803 smd: 26(1.125,-0.35)
HDR2X5_100MIL_SMT
  rect 3.175x1.27 smd: 1(-2.731,7.62) 2(2.731,7.62) 3(-2.731,5.08) 4(2.731,5.08) 5(-2.731,2.54) 6(2.731,2.54) 7(-2.731,0) 8(2.731,0) 9(-2.731,-2.54) 10(2.731,-2.54)
HDR2X6_100MIL
  rect 1.524x1.524 hole 1.016: 1(0,0)
  round 1.524 hole 1.016: 2(0,-2.54) 3(0,-5.08) 4(0,-7.62) 5(0,-10.16) 6(0,-12.7) 7(2.54,0) 8(2.54,-2.54) 9(2.54,-5.08) 10(2.54,-7.62) 11(2.54,-10.16) 12(2.54,-12.7)
HDR_1X6_100MIL
  rect 1.6x1.6 hole 1: 1(0,0)
  round 1.6 hole 1: 2(2.54,0) 3(5.08,0) 4(7.62,0) 5(10.16,0) 6(12.7,0)
HDR_1X8_100MIL
  rect 1.6x1.6 hole 1: 1(0,0)
  round 1.6 hole 1: 2(2.54,0) 3(5.08,0) 4(7.62,0) 5(10.16,0) 6(12.7,0) 7(15.24,0) 8(17.78,0)
HDR_1X10_100MIL
  rect 1.6x1.6 hole 1: 1(0,0)
  round 1.6 hole 1: 2(2.54,0) 3(5.08,0) 4(7.62,0) 5(10.16,0) 6(12.7,0) 7(15.24,0) 8(17.78,0) 9(20.32,0) 10(22.86,0)
HDR_2X3_100MIL_TH
  rect 1.626x1.626 hole 1.118: 1(0,0)
  round 1.626 hole 1.118: 2(2.54,0) 3(0,-2.54) 4(2.54,-2.54) 5(0,-5.08) 6(2.54,-5.08)
HDR_2X20_100MIL_TH_SR
  rect 1.6x1.6 hole 1.1: 1(0,0)
  round 1.6 hole 1.1: 2(0,2.54) 3(2.54,0) 4(2.54,2.54) 5(5.08,0) 6(5.08,2.54) 7(7.62,0) 8(7.62,2.54) 9(10.16,0) 10(10.16,2.54) 11(12.7,0) 12(12.7,2.54) 13(15.24,0) 14(15.24,2.54) 15(17.78,0) 16(17.78,2.54) 17(20.32,0) 18(20.32,2.54) 19(22.86,0) 20(22.86,2.54) 21(25.4,0) 22(25.4,2.54) 23(27.94,0) 24(27.94,2.54) 25(30.48,0) 26(30.48,2.54) 27(33.02,0) 28(33.02,2.54) 29(35.56,0) 30(35.56,2.54) 31(38.1,0) 32(38.1,2.54) 33(40.64,0) 34(40.64,2.54) 35(43.18,0) 36(43.18,2.54) 37(45.72,0) 38(45.72,2.54) 39(48.26,0) 40(48.26,2.54)
IND_0603
  rect 1.016x1.016 smd: 1(-0.762,0) 2(0.762,0)
IND_744028004
  rect 3.2x1.016 smd: 1(0,1.1) 2(0,-1.1)
JACK-DC_2MM_WE
  oval 4x1.8 hole 3x0.8: 1(0,-5.8) 2(0,0)
  oval 1.8x4 hole 0.8x3: 3(-4.8,-2.8)
LAN_XFMR_749020010A
  rect 0.762x1.905 smd: 1(-6.985,-7.303) 2(-5.715,-7.303) 3(-4.445,-7.303) 4(-3.175,-7.303) 5(-1.905,-7.303) 6(-0.635,-7.303) 7(0.635,-7.303) 8(1.905,-7.303) 9(3.175,-7.303) 10(4.445,-7.303) 11(5.715,-7.303) 12(6.985,-7.303) 13(6.985,7.303) 14(5.715,7.303) 15(4.445,7.303) 16(3.175,7.303) 17(1.905,7.303) 18(0.635,7.303) 19(-0.635,7.303) 20(-1.905,7.303) 21(-3.175,7.303) 22(-4.445,7.303) 23(-5.715,7.303) 24(-6.985,7.303)
LED_0603
  rect 0.787x0.991 smd: 1(-0.813,0) 2(0.813,0)
MSOP-8
  rect 0.432x0.889 smd: 1(-0.975,-2.17) 2(-0.325,-2.17) 3(0.325,-2.17) 4(0.975,-2.17) 5(0.975,2.17) 6(0.325,2.17) 7(-0.325,2.17) 8(-0.975,2.17)
MSOP-10_SI5351
  rect 1.4x0.3 smd: 1(-2.2,1) 2(-2.2,0.5) 3(-2.2,0) 4(-2.2,-0.5) 5(-2.2,-1) 6(2.2,-1) 7(2.2,-0.5) 8(2.2,0) 9(2.2,0.5) 10(2.2,1)
POWERDI123
  rect 2.2x1.4 smd: 1(0.95,0)
  rect 0.9x1.4 smd: 2(-1.6,0)
QFN56
  oval 0.813x0.279 smd: 1(-3.9,3.25) 2(-3.9,2.75) 3(-3.9,2.25) 4(-3.9,1.75) 5(-3.9,1.25) 6(-3.9,0.75) 7(-3.9,0.25) 8(-3.9,-0.25) 9(-3.9,-0.75) 10(-3.9,-1.25) 11(-3.9,-1.75) 12(-3.9,-2.25) 13(-3.9,-2.75) 14(-3.9,-3.25) 29(3.9,-3.25) 30(3.9,-2.75) 31(3.9,-2.25) 32(3.9,-1.75) 33(3.9,-1.25) 34(3.9,-0.75) 35(3.9,-0.25) 36(3.9,0.25) 37(3.9,0.75) 38(3.9,1.25) 39(3.9,1.75) 40(3.9,2.25) 41(3.9,2.75) 42(3.9,3.25)
  oval 0.279x0.813 smd: 15(-3.25,-3.9) 16(-2.75,-3.9) 17(-2.25,-3.9) 18(-1.75,-3.9) 19(-1.25,-3.9) 20(-0.75,-3.9) 21(-0.25,-3.9) 22(0.25,-3.9) 23(0.75,-3.9) 24(1.25,-3.9) 25(1.75,-3.9) 26(2.25,-3.9) 27(2.75,-3.9) 28(3.25,-3.9) 43(3.25,3.9) 44(2.75,3.9) 45(2.25,3.9) 46(1.75,3.9) 47(1.25,3.9) 48(0.75,3.9) 49(0.25,3.9) 50(-0.25,3.9) 51(-0.75,3.9) 52(-1.25,3.9) 53(-1.75,3.9) 54(-2.25,3.9) 55(-2.75,3.9) 56(-3.25,3.9)
  rect 5.842x5.842 smd: 57(0,0)
RJ45_615008140121
  round 3.25 hole 3.25 unplated: (-5.715,0) (5.715,0)
  round 1.4 hole 0.9: 1(-4.445,6.35) 2(-3.175,8.89) 3(-1.905,6.35) 4(-0.635,8.89) 5(0.635,6.35) 6(1.905,8.89) 7(3.175,6.35) 8(4.445,8.89)
  round 2.1 hole 1.6: 13(-7.8,-3.05) 14(7.8,-3.05)
SI510
  rect 1.55x1.95 smd: 1(-2.54,-2.1) 2(0,-2.1) 3(2.54,-2.1) 4(2.54,2.1) 5(0,2.1) 6(-2.54,2.1)
SOD128_CFP5
  rect 2.362x1.905 smd: 1(-1.981,0) 2(1.981,0)
SOIC-16_EPCQ
  rect 0.61x1.524 smd: 1(-4.445,-4.8) 2(-3.175,-4.8) 3(-1.905,-4.8) 4(-0.635,-4.8) 5(0.635,-4.8) 6(1.905,-4.8) 7(3.175,-4.8) 8(4.445,-4.8) 9(4.445,4.8) 10(3.175,4.8) 11(1.905,4.8) 12(0.635,4.8) 13(-0.635,4.8) 14(-1.905,4.8) 15(-3.175,4.8) 16(-4.445,4.8)
SOT23
  rect 1x1.4 smd: 1(-0.95,-1.1) 2(0.95,-1.1) 3(0,1.1)
SOT23-3
  rect 1x1.4 smd: 1(-0.95,-1.1) 2(0.95,-1.1) 3(0,1.1)
SOT23-6L
  rect 0.6x1.4 smd: 1(-0.95,-1.3) 2(0,-1.3) 3(0.95,-1.3) 4(0.95,1.3) 5(0,1.3) 6(-0.95,1.3)
SOT-23
  rect 1.016x1.422 smd: D(0,1.1) G(-0.95,-1.1) S(0.95,-1.1)
SOT-23_BZX84
  rect 1.016x1.422 smd: 1(-0.95,-1.1) 2(0.95,-1.1) 3(0,1.1)
SOT-143
  rect 0.864x0.889 smd: 1(-0.914,0.762)
  rect 0.864x0.508 smd: 2(-0.914,-0.965) 3(0.94,-0.965) 4(0.94,0.965)
SOT-323
  rect 0.66x1.118 smd: 1(-0.65,-1.059) 2(0.65,-1.059) 3(0,1.059)
TFBGA-24_6X8
  round 0.35 smd: A1(-2,2) A2(-1,2) A3(0,2) A4(1,2) A5(2,2) B1(-2,1) B2(-1,1) B3(0,1) B4(1,1) B5(2,1) C1(-2,0) C2(-1,0) C3(0,0) C4(1,0) C5(2,0) D1(-2,-1) D2(-1,-1) D3(0,-1) D4(1,-1) D5(2,-1) E1(-2,-2) E2(-1,-2) E3(0,-2) E4(1,-2) E5(2,-2)
TP_020RD_SMT
  round 0.508 smd: 1(0,0)
TP_040RD_SMT
  round 1.016 smd: 1(0,0)
U256
  round 0.34 smd: A1(-6,6) A2(-5.2,6) A3(-4.4,6) A4(-3.6,6) A5(-2.8,6) A6(-2,6) A7(-1.2,6) A8(-0.4,6) A9(0.4,6) A10(1.2,6) A11(2,6) A12(2.8,6) A13(3.6,6) A14(4.4,6) A15(5.2,6) A16(6,6) B1(-6,5.2) B2(-5.2,5.2) B3(-4.4,5.2) B4(-3.6,5.2) B5(-2.8,5.2) B6(-2,5.2) B7(-1.2,5.2) B8(-0.4,5.2) B9(0.4,5.2) B10(1.2,5.2) B11(2,5.2) B12(2.8,5.2) B13(3.6,5.2) B14(4.4,5.2) B15(5.2,5.2) B16(6,5.2) C1(-6,4.4) C2(-5.2,4.4) C3(-4.4,4.4) C4(-3.6,4.4) C5(-2.8,4.4) C6(-2,4.4) C7(-1.2,4.4) C8(-0.4,4.4) C9(0.4,4.4) C10(1.2,4.4) C11(2,4.4) C12(2.8,4.4) C13(3.6,4.4) C14(4.4,4.4) C15(5.2,4.4) C16(6,4.4) D1(-6,3.6) D2(-5.2,3.6) D3(-4.4,3.6) D4(-3.6,3.6) D5(-2.8,3.6) D6(-2,3.6) D7(-1.2,3.6) D8(-0.4,3.6) D9(0.4,3.6) D10(1.2,3.6) D11(2,3.6) D12(2.8,3.6) D13(3.6,3.6) D14(4.4,3.6) D15(5.2,3.6) D16(6,3.6) E1(-6,2.8) E2(-5.2,2.8) E3(-4.4,2.8) E4(-3.6,2.8) E5(-2.8,2.8) E6(-2,2.8) E7(-1.2,2.8) E8(-0.4,2.8) E9(0.4,2.8) E10(1.2,2.8) E11(2,2.8) E12(2.8,2.8) E13(3.6,2.8) E14(4.4,2.8) E15(5.2,2.8) E16(6,2.8) F1(-6,2) F2(-5.2,2) F3(-4.4,2) F4(-3.6,2) F5(-2.8,2) F6(-2,2) F7(-1.2,2) F8(-0.4,2) F9(0.4,2) F10(1.2,2) F11(2,2) F12(2.8,2) F13(3.6,2) F14(4.4,2) F15(5.2,2) F16(6,2) G1(-6,1.2) G2(-5.2,1.2) G3(-4.4,1.2) G4(-3.6,1.2) G5(-2.8,1.2) G6(-2,1.2) G7(-1.2,1.2) G8(-0.4,1.2) G9(0.4,1.2) G10(1.2,1.2) G11(2,1.2) G12(2.8,1.2) G13(3.6,1.2) G14(4.4,1.2) G15(5.2,1.2) G16(6,1.2) H1(-6,0.4) H2(-5.2,0.4) H3(-4.4,0.4) H4(-3.6,0.4) H5(-2.8,0.4) H6(-2,0.4) H7(-1.2,0.4) H8(-0.4,0.4) H9(0.4,0.4) H10(1.2,0.4) H11(2,0.4) H12(2.8,0.4) H13(3.6,0.4) H14(4.4,0.4) H15(5.2,0.4) H16(6,0.4) J1(-6,-0.4) J2(-5.2,-0.4) J3(-4.4,-0.4) J4(-3.6,-0.4) J5(-2.8,-0.4) J6(-2,-0.4) J7(-1.2,-0.4) J8(-0.4,-0.4) J9(0.4,-0.4) J10(1.2,-0.4) J11(2,-0.4) J12(2.8,-0.4) J13(3.6,-0.4) J14(4.4,-0.4) J15(5.2,-0.4) J16(6,-0.4) K1(-6,-1.2) K2(-5.2,-1.2) K3(-4.4,-1.2) K4(-3.6,-1.2) K5(-2.8,-1.2) K6(-2,-1.2) K7(-1.2,-1.2) K8(-0.4,-1.2) K9(0.4,-1.2) K10(1.2,-1.2) K11(2,-1.2) K12(2.8,-1.2) K13(3.6,-1.2) K14(4.4,-1.2) K15(5.2,-1.2) K16(6,-1.2) L1(-6,-2) L2(-5.2,-2) L3(-4.4,-2) L4(-3.6,-2) L5(-2.8,-2) L6(-2,-2) L7(-1.2,-2) L8(-0.4,-2) L9(0.4,-2) L10(1.2,-2) L11(2,-2) L12(2.8,-2) L13(3.6,-2) L14(4.4,-2) L15(5.2,-2) L16(6,-2) M1(-6,-2.8) M2(-5.2,-2.8) M3(-4.4,-2.8) M4(-3.6,-2.8) M5(-2.8,-2.8) M6(-2,-2.8) M7(-1.2,-2.8) M8(-0.4,-2.8) M9(0.4,-2.8) M10(1.2,-2.8) M11(2,-2.8) M12(2.8,-2.8) M13(3.6,-2.8) M14(4.4,-2.8) M15(5.2,-2.8) M16(6,-2.8) N1(-6,-3.6) N2(-5.2,-3.6) N3(-4.4,-3.6) N4(-3.6,-3.6) N5(-2.8,-3.6) N6(-2,-3.6) N7(-1.2,-3.6) N8(-0.4,-3.6) N9(0.4,-3.6) N10(1.2,-3.6) N11(2,-3.6) N12(2.8,-3.6) N13(3.6,-3.6) N14(4.4,-3.6) N15(5.2,-3.6) N16(6,-3.6) P1(-6,-4.4) P2(-5.2,-4.4) P3(-4.4,-4.4) P4(-3.6,-4.4) P5(-2.8,-4.4) P6(-2,-4.4) P7(-1.2,-4.4) P8(-0.4,-4.4) P9(0.4,-4.4) P10(1.2,-4.4) P11(2,-4.4) P12(2.8,-4.4) P13(3.6,-4.4) P14(4.4,-4.4) P15(5.2,-4.4) P16(6,-4.4) R1(-6,-5.2) R2(-5.2,-5.2) R3(-4.4,-5.2) R4(-3.6,-5.2) R5(-2.8,-5.2) R6(-2,-5.2) R7(-1.2,-5.2) R8(-0.4,-5.2) R9(0.4,-5.2) R10(1.2,-5.2) R11(2,-5.2) R12(2.8,-5.2) R13(3.6,-5.2) R14(4.4,-5.2) R15(5.2,-5.2) R16(6,-5.2) T1(-6,-6) T2(-5.2,-6) T3(-4.4,-6) T4(-3.6,-6) T5(-2.8,-6) T6(-2,-6) T7(-1.2,-6) T8(-0.4,-6) T9(0.4,-6) T10(1.2,-6) T11(2,-6) T12(2.8,-6) T13(3.6,-6) T14(4.4,-6) T15(5.2,-6) T16(6,-6)
unnamed#2
  round 1.016 smd: 1(0,0)
unnamed#3
  round 6.35 hole 3.175: (0,0)
UQFN16
  rect 0.559x0.203 smd: 1(-1.05,1) 2(-1.05,0.6) 3(-1.05,0.2) 4(-1.05,-0.2) 5(-1.05,-0.6) 6(-1.05,-1) 9(1.05,-1) 10(1.05,-0.6) 11(1.05,-0.2) 12(1.05,0.2) 13(1.05,0.6) 14(1.05,1)
  rect 0.203x0.559 smd: 7(-0.2,-1.175) 8(0.2,-1.175) 15(0.2,1.175) 16(-0.2,1.175)
VQFN-48_PEF7071
  oval 0.914x0.279 smd: 1(-3.5,2.75) 2(-3.5,2.25) 3(-3.5,1.75) 4(-3.5,1.25) 5(-3.5,0.75) 6(-3.5,0.25) 7(-3.5,-0.25) 8(-3.5,-0.75) 9(-3.5,-1.25) 10(-3.5,-1.75) 11(-3.5,-2.25) 12(-3.5,-2.75) 25(3.5,-2.75) 26(3.5,-2.25) 27(3.5,-1.75) 28(3.5,-1.25) 29(3.5,-0.75) 30(3.5,-0.25) 31(3.5,0.25) 32(3.5,0.75) 33(3.5,1.25) 34(3.5,1.75) 35(3.5,2.25) 36(3.5,2.75)
  oval 0.279x0.914 smd: 13(-2.75,-3.5) 14(-2.25,-3.5) 15(-1.75,-3.5) 16(-1.25,-3.5) 17(-0.75,-3.5) 18(-0.25,-3.5) 19(0.25,-3.5) 20(0.75,-3.5) 21(1.25,-3.5) 22(1.75,-3.5) 23(2.25,-3.5) 24(2.75,-3.5) 37(2.75,3.5) 38(2.25,3.5) 39(1.75,3.5) 40(1.25,3.5) 41(0.75,3.5) 42(0.25,3.5) 43(-0.25,3.5) 44(-0.75,3.5) 45(-1.25,3.5) 46(-1.75,3.5) 47(-2.25,3.5) 48(-2.75,3.5)
  rect 5.207x5.207 smd: 49(0,0)
WURTH_6X3P5_TACT_SWITCH
  rect 2.311x1.499 smd: 1(-3.356,0) 2(3.356,0)
WURTH_USB_MINI-B
  oval 1.016x1.143 hole 0.711: 1(-1.6,0.9) 2(-0.8,-0.3) 3(0,0.9) 4(0.8,-0.3) 5(1.6,0.9)
  oval 1.626x2.616 hole 0.914x1.905: 6(-3.65,0) 7(3.65,0) 8(-3.65,-4.65) 9(3.65,-4.65)
XTAL_FA-128
  rect 0.94x0.838 smd: 1(-0.725,-0.575) 2(0.725,-0.575) 3(0.725,0.575) 4(-0.725,0.575)
XTAL_FA-238
  rect 1.4x1.2 smd: 1(-1.1,-0.8) 2(1.1,-0.8) 3(1.1,0.8) 4(-1.1,0.8)

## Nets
1.8V_VSENSE: C104.2 R197.2 U26.5(VSENSE)
2.5V_VSENSE: C103.2 R198.2 U27.5(VSENSE)
3.3V_SI510: C74.2 L12.2 U20.2(OE) U20.6(VDD)
5V_DCIN: D41.2 J12.1 R164.1 R300.1
GND: C1.2 C2.1 C4.2 C5.2 C6.1 C7.1 C8.1 C9.1 C10.1 C11.1 C12.1 C13.1 C14.1 C15.1 C16.1 C17.1 C18.1 C40.2 C41.1 C42.1 C43.1 C44.2 C45.1 C46.2 C47.2 C48.2 C49.2 C50.1 C51.1 C52.1 C53.2 C54.1 C55.1 C56.1 C57.1 C58.1 C59.2 C60.1 C61.1 C62.1 C63.2 C64.1 C65.1 C66.1 C67.1 C72.1 C73.1 C74.1 C76.2 C83.2 C85.2 C86.2 C87.2 C88.1 C89.2 C96.2 C98.2 C99.2 C100.2 C101.1 C102.2 C105.2 C106.2 C107.2 C108.2 C109.2 C110.2 C111.2 C112.2 C113.1 C114.1 C115.2 C117.1 C120.1 C122.1 C124.2 C129.2 C130.2 C134.2 C136.2 C138.1 C139.1 C141.2 C142.2 C143.1 C146.2 C151.2 C153.1 C155.1 C156.2 C157.1 C160.2 C161.2 C162.2 C163.2 C164.2 C165.2 C166.2 C176.2 C177.2 C178.1 C179.1 C180.1 C181.1 C182.2 C183.2 C184.1 C185.2 C189.2 C190.2 C193.2 C194.2 C195.2 C196.2 C197.2 C202.2 C204.2 C205.2 C206.2 C207.2 C208.2 C209.2 C211.2 D28.1(ANODE) J1.2 J1.10 J2.10 J4.6 J4.7 J5.7 J8.5 J8.11 J10.12 J10.30 J12.2 J12.3 J17.5(GND) J18.6 L14.1 Q5.2(SOURCE) R6.2 R8.1 R13.1 R18.2 R20.2 R23.2 R27.2 R28.1 R32.1 R40.1 R45.2 R58.2 R92.1 R101.1 R108.1 R109.1 R110.1 R112.1 R114.1 R173.2 R181.1 R201.2 R213.2 R240.1 R241.1 R242.1 R291.2 R293.1 R298.2 R309.1 S1.1 S2.1 S3.1 S4.1 S5.1 S6.1 SW1.1(A1) SW1.2(A2) SW1.3(A3) SW1.4(A4) TP12.1(TP) TP13.1(TP) TP14.1(TP) TP15.1(TP) TP16.1(TP) TP17.1(TP) U1.B2(GND#B2) U1.B15(GND#B15) U1.C5(GND#C5) U1.C12(GND#C12) U1.D5(GND#D5) U1.D7(GND#D7) U1.D10(GND#D10) U1.E2(CLK0, DIFFCLK_0P) U1.E4(GND#E4) U1.E5(GNDA3) U1.E12(GNDA2) U1.E13(GND#E13) U1.F1(GND#F1) U1.F2(GND#F2) U1.F6(GND#F6) U1.F10(GND#F10) U1.G4(GND#G4) U1.G5(GND#G5) U1.G11(GND#G11) U1.G13(GND#G13) U1.H7(GND#H7) U1.H8(GND#H8) U1.H9(GND#H9) U1.H10(GND#H10) U1.H15(GND#H15) U1.H16(GND#H16) U1.J7(GND#J7) U1.J8(GND#J8) U1.J9(GND#J9) U1.J10(GND#J10) U1.J11(GND#J11) U1.K4(GND#K4) U1.K6(GND#K6) U1.K8(GND#K8) U1.K12(GND#K12) U1.K13(GND#K13) U1.L9(GND#L9) U1.L10(GND#L10) U1.L11(GND#L11) U1.M1(CLK3, DIFFCLK_1N) U1.M2(CLK2, DIFFCLK_1P) U1.M4(GND#M4) U1.M5(GNDA1) U1.M12(GNDA4) U1.M13(GND#M13) U1.N7(GND#N7) U1.N10(GND#N10) U1.P5(GND#P5) U1.P12(GND#P12) U1.R2(GND#R2) U1.R8(CLK15, DIFFCLK_6P) U1.R9(CLK13, DIFFCLK_7P) U1.R15(GND#R15) U1.T9(CLK12, DIFFCLK_7N) U2.10(GND) U3.A1(GND__A1) U3.A13(GND__A13) U3.B8(GND__B8) U3.C3(GND__C3) U3.D5(GND__D5) U3.E11(GND__E11) U3.E13(IO_6_E13/CLK3N/DIFFIO_RX_R16N) U3.F3(GND__F3) U3.F9(IO_6_F9/DPCLK3/DIFFIO_RX_R26P) U3.F10(IO_6_F10/DPCLK2/DIFFIO_RX_R26N) U3.F13(IO_6_F13/CLK3P/DIFFIO_RX_R16P) U3.G7(GND__G7) U3.G9(IO_6_G9/CLK2P/DIFFIO_RX_R14P) U3.G10(IO_6_G10/CLK2N/DIFFIO_RX_R14N) U3.H4(IO_2_H4/CLK1P/DIFFIO_RX_L20P) U3.H6(IO_2_H6/CLK0P/DIFFIO_RX_L18P) U3.H12(GND__H12) U3.J4(GND__J4) U3.L9(GND__L9) U3.M6(GND__M6) U3.N1(GND__N1) U3.N2(IO_2_N2/DPCLK0/DIFFIO_RX_L22N) U3.N3(IO_2_N3/DPCLK1/DIFFIO_RX_L22P) U3.N13(GND__N13) U4.1(GND) U5.3(GND) U6.6(AGND0) U6.10(AGND1) U6.12(GND0) U6.14(RESERVED) U6.26(GND1) U6.28(GND2) U6.41(GND3) U6.53(GND4) U6.56(GND5) U6.57(EXPOSED_PAD) U13.B3(VSS2) U13.C1(VSSQ1) U13.E5(VSSQ2) U14.49(EPAD) U15.2(GND) U16.2(GND) U20.3(GND) U23.2(PGND#2) U23.3(PGND#3) U23.8(PGND#8) U23.9(PGND#9) U23.15(AGND) U23.25(PGND#25) U23.26(PGND#26) U25.2(PGND#2) U25.3(PGND#3) U25.8(PGND#8) U25.9(PGND#9) U25.15(AGND) U25.25(PGND#25) U25.26(PGND#26) U26.2(PGND#2) U26.3(PGND#3) U26.6(AGND) U27.2(PGND#2) U27.3(PGND#3) U27.6(AGND) U27.10(VS1) U27.11(VS0) U31.8(GND) Y1.2 Y1.4 Y2.2 Y2.4 Y3.2 Y3.4
GND_EARTH_ETH: C159.2 C164.1 J16.13(CGND1) J16.14(CGND2) R28.2
GND_EARTH_USB: C202.1 J17.6(SHELL1) J17.7(SHELL2) J17.8(SHELL3) J17.9(SHELL4) R293.2
VCC_1.2V: C97.1 C98.1 C99.1 C100.1 L15.1 R63.2 R66.2 R191.2 TP20.1(TP) U25.4(VOUT#4) U25.5(VOUT#5) U25.6(VOUT#6) U25.7(VOUT#7)
VCC_1.2V_EN: C101.2 R190.1 U25.18(ENABLE)
VCC_1.2V_FB: C97.2 R191.1 R192.2 U25.14(VFB)
VCC_1.2V_PG: R189.2 U3.H10(IO_5_H10/DIFFIO_RX_R8N) U25.17(POK)
VCC_1.8V: C40.1 C41.2 C42.2 C43.2 C104.1 C107.1 C108.1 C112.1 C183.1 C184.2 C185.1 R197.1 R236.1 R245.2 R261.2 R262.2 TP22.1(TP) U13.B4(VCC) U13.D1(VCCQ1) U13.E4(VCCQ2) U26.7(VOUT#7) U26.8(VOUT#8)
VCC_1.8V_EN: C114.2 R199.1 U26.12(ENABLE)
VCC_2.5V: C103.1 C109.1 C110.1 C111.1 C182.1 C189.1 R64.2 R68.2 R198.1 TP21.1(TP) U3.F11(VCCIO6__F11) U3.G11(VCCIO6__G11) U27.7(VOUT#7) U27.8(VOUT#8)
VCC_2.5V_EN: C113.2 R200.1 U27.12(ENABLE)
VCC_3.3V: C1.1 C2.2 C6.2 C7.2 C8.2 C9.2 C10.2 C11.2 C12.2 C13.2 C16.2 C18.2 C84.1 C85.1 C86.1 C87.1 C146.1 C151.1 C153.2 C155.2 C157.2 C190.1 J1.4 J2.4 J4.4 J8.6 J8.12 J10.29 L2.1 L3.1 L10.1 L12.1 L16.2 R9.1 R11.2 R29.2 R30.2 R33.1 R38.1 R39.1 R41.1 R42.1 R43.1 R46.1 R47.1 R50.2 R51.2 R52.2 R53.2 R54.2 R55.1 R56.1 R59.2 R60.1 R61.1 R77.2 R79.2 R135.1 R137.2 R138.1 R139.2 R140.1 R141.2 R142.1 R143.1 R144.2 R145.2 R146.2 R147.2 R148.2 R178.1 R180.2 R189.1 R214.1 R215.1 R265.2 R266.2 R269.2 R270.2 R280.1 R307.1 TP19.1(TP) U2.2(VCC) U3.C6(VCCIO8__C6) U3.C7(VCCIO8__C7) U3.C8(VCCIO8__C8) U3.F7(VCC_ONE__F7) U3.G3(VCCIO1B__G3) U3.G6(VCC_ONE__G6) U3.G8(VCC_ONE__G8) U3.H7(VCC_ONE__H7) U3.H11(VCCIO5__H11) U3.J3(VCCIO2__J3) U3.J11(VCCIO5__J11) U3.K3(VCCIO2__K3) U3.L6(VCCIO3__L6) U3.L7(VCCIO3__L7) U3.L8(VCCIO3__L8) U4.4(VCC) U6.3(AVCC0) U6.7(AVCC1) U6.11(VCC0) U6.17(VCC1) U6.27(VCC2) U6.32(VCC3) U6.43(VCC4) U6.55(VCC5) U15.5(VDD) U16.5(VDD) U23.4(VOUT#4) U23.5(VOUT#5) U23.6(VOUT#6) U23.7(VOUT#7)
VCC_3.3V_EN: C88.2 R179.1 U23.18(ENABLE)
VCC_3.3V_FB: C84.2 R180.1 R181.2 U23.14(VFB)
VCC_3.3V_PG: R178.2 U3.H13(IO_5_H13/DIFFIO_RX_R9N) U23.17(POK)
VCC_5V: C76.1 C83.1 C89.1 C96.1 C102.1 C105.1 C106.1 C165.1 C166.1 C200.2 C203.1 F1.1 F2.1 F3.1 L5.1 Q15.D R173.1 R179.2 R190.2 R199.2 R200.2 R235.1 R296.2 TP18.1(TP) U23.10(TST2) U23.11(TST1) U23.12(TST0) U23.16(AVIN) U23.19(PVIN#19) U23.20(PVIN#20) U25.10(TST2) U25.11(TST1) U25.12(TST0) U25.16(AVIN) U25.19(PVIN#19) U25.20(PVIN#20) U26.9(VS2) U26.10(VS1) U26.11(VS0) U26.13(AVIN) U26.14(PVIN) U27.9(VS2) U27.13(AVIN) U27.14(PVIN)
VCC_5V_AR1: F2.2 J4.5 R275.2
VCC_5V_AR2: F3.2 J18.2
VCC_5V_GPIO: F1.2 J10.11
VCC_5V_IN: C201.1 C203.2 C210.2 C211.1 D20.1(CATHODE) D41.1 Q15.S Q29.2(E) Q30.S R164.2 R165.2 R289.1 R292.1 R296.1
VCCA_ISENSE: C22.2 R72.2 R85.2 U8.5(VOUT)
VCCINT_ISENSE: C20.2 R71.2 R86.2 U7.5(VOUT)
VCCIO_3.3V_ISENSE: C28.2 R81.2 R89.2 U11.5(VOUT)
24M_XTALIN: C4.1 U6.5(XTALIN) Y1.1
24M_XTALOUT: C5.1 U6.4(XTALOUT) Y1.3
A0+: C169.1 R216.2 R217.2 U32.3(VINA+)
A1+: C170.1 R218.2 R219.2 U32.5(VINB+)
A2+: C171.1 R220.2 R221.2 U33.3(VINA+)
A3+: C172.1 R222.2 R223.2 U33.5(VINB+)
A4+: C174.1 R224.2 R225.2 U34.3(VINA+)
A5+: C175.1 R226.2 R227.2 U34.5(VINB+)
A_GND: C19.1 C20.1 C22.1 C23.1 C26.1 C28.1 C29.2 C30.2 C31.2 C32.2 C33.2 C34.2 C35.2 C36.2 C37.2 C38.2 C39.2 C168.2 C169.2 C170.2 C171.2 C172.2 C173.2 C174.2 C175.2 C188.2 C212.2 C213.1 L14.2 R71.1 R72.1 R81.1 R216.1 R218.1 R220.1 R222.1 R224.1 R226.1 U3.E2(REFGND__E2) U7.4(V-) U8.4(V-) U11.4(V-) U12.3(GND) U32.4(VSS) U33.4(VSS) U34.4(VSS)
ADC1IN1: C32.1 R84.1 U3.D1(IO_1A_D1/ADC1IN1/DIFFIO_RX_L1N)
ADC1IN2: C33.1 R85.1 U3.C2(IO_1A_C2/ADC1IN2/DIFFIO_RX_L1P)
ADC1IN3: C34.1 R86.1 U3.E3(IO_1A_E3/ADC1IN3/DIFFIO_RX_L3N)
ADC1IN4: C35.1 R87.1 U3.E4(IO_1A_E4/ADC1IN4/DIFFIO_RX_L3P)
ADC1IN5: C36.1 R88.1 U3.C1(IO_1A_C1/ADC1IN5/DIFFIO_RX_L5N)
ADC1IN6: C37.1 R89.1 U3.B1(IO_1A_B1/ADC1IN6/DIFFIO_RX_L5P)
ADC1IN7: C38.1 R90.1 U3.F1(IO_1A_F1/ADC1IN7/DIFFIO_RX_L7N)
ADC1IN8: C39.1 R91.1 U3.E1(IO_1A_E1/ADC1IN8/DIFFIO_RX_L7P)
ANA_VREF: J5.8 R308.1
ANAIN1: C29.1 R83.1 U3.D2(ANAIN1__D2)
ARDUINO_ADC_SCL: R215.2 R279.2 U1.D8(IO_B8_1) U3.L12(IO_5_L12/DIFFIO_RX_R2N)
ARDUINO_ADC_SDA: R214.2 R278.2 U1.C8(IO_B8_0) U3.K11(IO_5_K11/DIFFIO_RX_R2P)
ARDUINO_AMP0: R88.2 U32.1(VOUTA) U32.2(VINA-)
ARDUINO_AMP1: R83.2 U32.6(VINB-) U32.7(VOUTB)
ARDUINO_AMP2: R84.2 U33.1(VOUTA) U33.2(VINA-)
ARDUINO_AMP3: R91.2 U33.6(VINB-) U33.7(VOUTB)
ARDUINO_AMP4: R90.2 U34.1(VOUTA) U34.2(VINA-)
ARDUINO_AMP5: R87.2 U34.6(VINB-) U34.7(VOUTB)
ARDUINO_ANA0: J6.1 R217.1
ARDUINO_ANA1: J6.2 R219.1
ARDUINO_ANA2: J6.3 R221.1
ARDUINO_ANA3: J6.4 R223.1
ARDUINO_ANA4: J6.5 R225.1
ARDUINO_ANA5: J6.6 R227.1
ARDUINO_IO0: J7.1 U1.B1(IO_B1_0)
ARDUINO_IO1: J7.2 U1.C2(IO, DIFFIO_L3P)
ARDUINO_IO2: J7.3 U1.F3(IO, VREFB1N0)
ARDUINO_IO3: J7.4 U1.D1(IO, DIFFIO_L4N)
ARDUINO_IO4: J7.5 U1.G2(IO, DIFFIO_L6P)
ARDUINO_IO5: J7.6 U1.G1(IO, DIFFIO_L6N)
ARDUINO_IO6: J7.7 U1.J2(IO, DIFFIO_L7P)
ARDUINO_IO7: J7.8 U1.J1(IO, DIFFIO_L7N)
ARDUINO_IO8: J5.1 U1.K2(IO, DIFFIO_L10P)
ARDUINO_IO9: J5.2 U1.K5(IO, RUP1)
ARDUINO_IO10: J5.3 U1.L4(IO, RDN1)
ARDUINO_IO11: J5.4 J18.4 U1.K1(IO, DIFFIO_L10N)
ARDUINO_IO12: J5.5 J18.1 U1.L2(IO, DIFFIO_L11P)
ARDUINO_IO13: J5.6 J18.3 U1.L1(IO, DIFFIO_L11N)
ARDUINO_RSTN: J4.3 J18.5 R288.2 U1.L3(IO, VREFB2N0)
ARDUINO_SCL: J5.10 R277.2 U1.N1(IO, DIFFIO_L13N)
ARDUINO_SDA: J5.9 R276.2 U1.N2(IO, DIFFIO_L13P)
C10_AS_ASDO: U1.C1(IO, DIFFIO_L3N, DATA1, ASDO) U2.15(DATA0)
C10_AS_CSN: U1.D2(IO, DIFFIO_L4P, FLASH_NCE, NCSO) U2.7(NCS)
C10_AS_DATA0: R10.1 U1.H2(IO, DATA0)
C10_AS_DCLK: U1.H1(DCLK) U2.16(DCLK)
C10_CLK50M: R162.2 U1.E1(CLK1, DIFFCLK_0N)
C10_CLK50M_R: R162.1 U20.5(CLKN/2)
C10_CLK_ADJ: R155.2 U1.E16(CLK5, DIFFCLK_2N)
C10_CONF_DONE: R16.2 U1.H14(CONF_DONE) U3.L2(IO_2_L2)
C10_CRC_ERROR: R246.2 U1.G15(IO, DIFFIO_R5P, CRC_ERROR) U3.M1(IO_2_M1/DIFFIO_RX_L21N)
C10_DEV_OE: R207.2 U1.J16(IO, DIFFIO_R9N, DEV_OE)
C10_INIT_DONE: R21.2 U1.G16(IO, DIFFIO_R5N, INIT_DONE) U3.K2(IO_2_K2/DIFFIO_RX_L28P)
C10_JTAG_TCK: R6.1 U1.H3(TCK) U3.E10(IO_6_E10/DIFFIO_RX_R31P)
C10_JTAG_TDI: R4.2 U1.H4(TDI) U3.A12(IO_6_A12/DIFFIO_RX_R30N)
C10_JTAG_TDO: U1.J4(TDO) U3.D12(IO_6_D12/DIFFIO_RX_R33P)
C10_JTAG_TMS: R7.2 U1.J5(TMS) U3.D9(IO_6_D9/DIFFIO_RX_R31N)
C10_M10_IO0: U1.E8(IO, DIFFIO_T10N, DATA2) U3.K8(IO_3_K8/DIFFIO_TX_RX_B14P)
C10_M10_IO1: U1.E7(IO, DATA5) U3.J8(IO_3_J8/DIFFIO_TX_RX_B14N)
C10_M10_IO2: U1.F8(IO, DIFFIO_T10P, DATA3) U3.L10(IO_3_L10/DIFFIO_TX_RX_B16P)
